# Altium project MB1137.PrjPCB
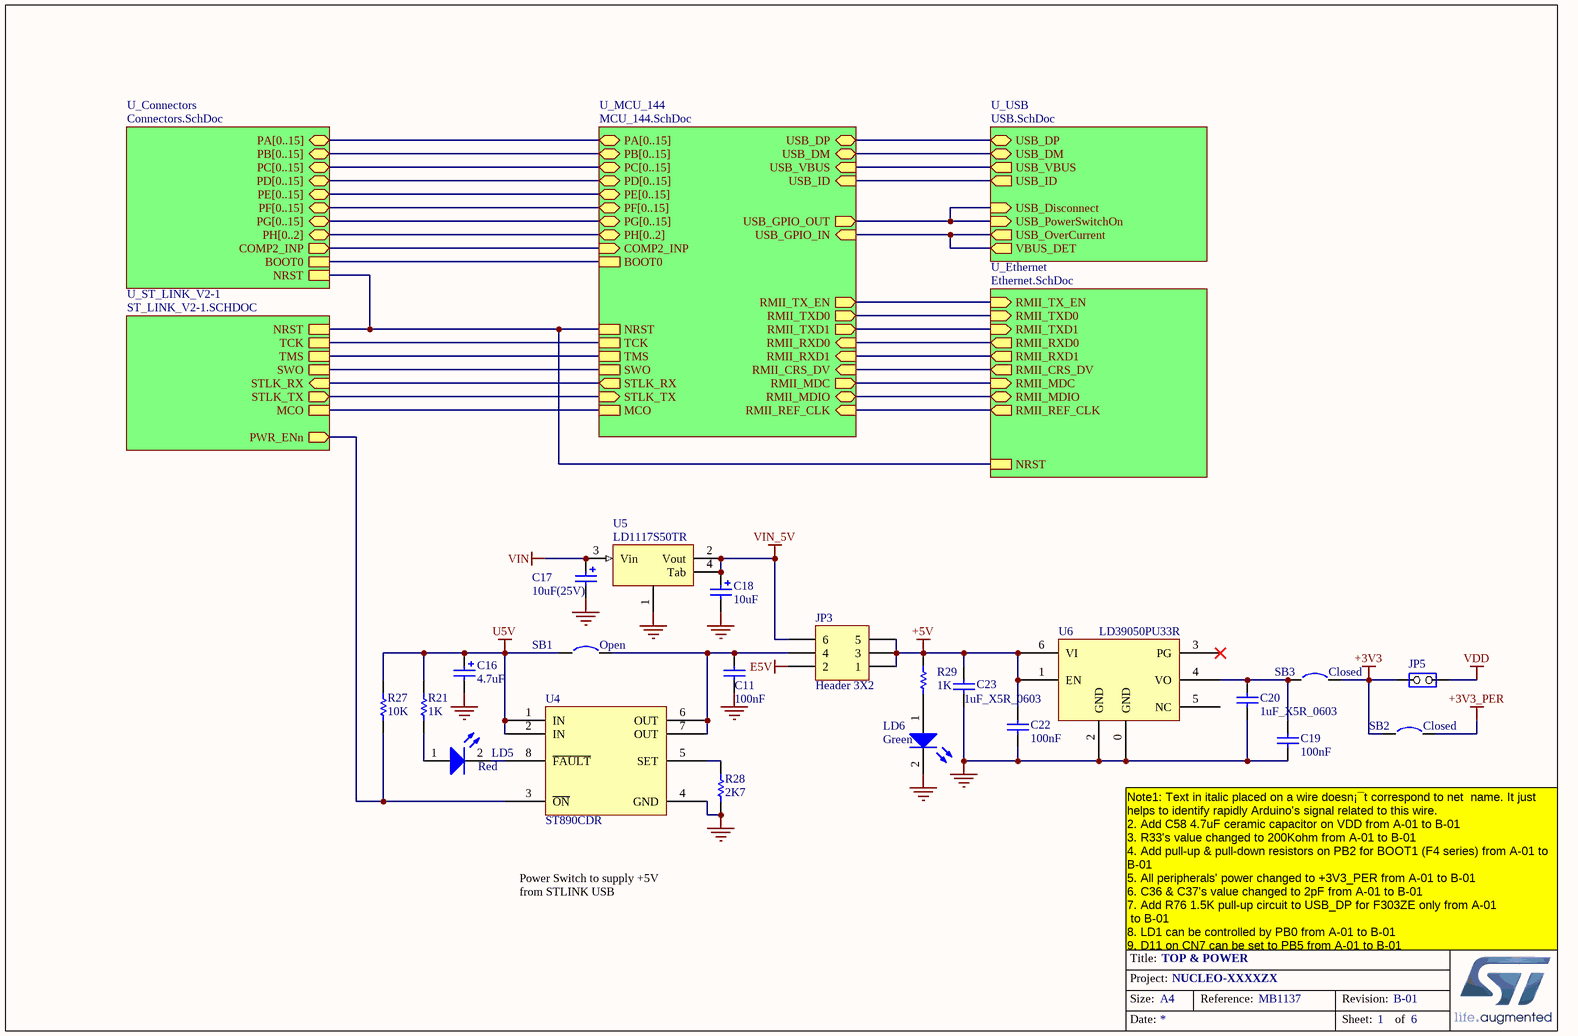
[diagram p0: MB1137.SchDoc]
6 sheets, 293 parts. Net scope: hierarchical (ports join the sheet entries above them; power ports are global).
Sheets:
  MB1137.SchDoc
    U_Connectors = Connectors.SchDoc
    U_ST_LINK_V2-1 = ST_LINK_V2-1.SCHDOC
    U_Ethernet = Ethernet.SchDoc
    U_MCU_144 = MCU_144.SchDoc
    U_USB = USB.SchDoc

## Sheet MB1137.SchDoc: TOP & POWER
size A4; DocumentNumber: MB1137; Revision: B-01; SheetNumber: 1; SheetTotal: 6; Project: NUCLEO-XXXXZX

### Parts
C11  100nF  [0603C]
C16  4.7uF  [TAN-A]
C17  10uF(25V)  [TAN-B]
C18  10uF  [TAN-A]
C19  100nF  [0603C]
C20  1uF_X5R_0603  [0603C]
C22  100nF  [0603C]
C23  1uF_X5R_0603  [0603C]
JP3  Header 3X2  [HDR_3x2_2R54_V_M]
JP5  (no value)  [HDR_1x2_2R54_V_M_S]
LD5  Red  [0603D-R]
LD6  Green  [0603D-G]
R21  1K  [0603R]
R27  10K  [0603R]
R28  2K7  [0603R]
R29  1K  [0603R]
SB1  Open  [SB_0603]
SB2  Closed  [SB_0603]
SB3  Closed  [SB_0603]
U4  ST890CDR  [SOIC8_1R27_4R9X6]
U5  LD1117S50TR  [SOT-223]
U6  LD39050PU33R  [DFN6_0R95_3x3_TP]

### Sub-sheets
U_Connectors = Connectors.SchDoc: PA[0..15] (bidir), PB[0..15] (bidir), PC[0..15] (bidir), NRST, BOOT0, PD[0..15] (bidir), PE[0..15] (bidir), PF[0..15] (bidir), PG[0..15] (bidir), PH[0..2] (bidir), COMP2_INP (out)
U_Ethernet = Ethernet.SchDoc: RMII_TXD0 (in), RMII_TX_EN (in), RMII_RXD0 (out), RMII_REF_CLK (out), RMII_CRS_DV (out), RMII_MDC (in), RMII_MDIO (bidir), NRST, RMII_TXD1 (in), RMII_RXD1 (out)
U_MCU_144 = MCU_144.SchDoc: NRST, MCO, STLK_TX (in), STLK_RX (out), PA[0..15] (bidir), PB[0..15] (bidir), PC[0..15] (bidir), TCK, TMS, SWO, BOOT0, PD[0..15] (bidir), PE[0..15] (bidir), PF[0..15] (bidir), PG[0..15] (bidir), PH[0..2] (bidir), USB_DM (bidir), USB_DP (bidir), USB_GPIO_OUT (out), USB_GPIO_IN (in), USB_ID (in), USB_VBUS (in), RMII_TXD0 (out), RMII_TX_EN (out), RMII_RXD0 (in), RMII_REF_CLK (in), RMII_CRS_DV (in), RMII_MDC (out), RMII_MDIO (bidir), RMII_TXD1 (out), RMII_RXD1 (in), COMP2_INP (in)
U_ST_LINK_V2-1 = ST_LINK_V2-1.SCHDOC: TMS, TCK, MCO, NRST, STLK_RX (in), STLK_TX (out), SWO, PWR_ENn (out)
U_USB = USB.SchDoc: USB_PowerSwitchOn (in), USB_OverCurrent (out), USB_DM (bidir), USB_DP (bidir), USB_ID (out), USB_VBUS (out), USB_Disconnect (in), VBUS_DET (out)

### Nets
+3V3: JP5.1(COMMON) SB2.1 SB3.2
+3V3_PER: SB2.2
+5V: C22.2 C23.1 JP3.1 JP3.3 JP3.5 R29.2 U6.1(EN) U6.6(VI)
E5V: JP3.2
GND: C11.1 C16.2 C17.2 C18.2 C19.1 C20.2 C22.1 C23.2 LD6.2(K) R28.1 U4.4(GND) U5.1 U6.0(GND) U6.2(GND)
U5V: C16.1 R21.1 R27.1 SB1.1 U4.1(IN) U4.2(IN)
VDD: JP5.2(NO)
VIN: C17.1 U5.3(Vin)
VIN_5V: C18.1 JP3.6 U5.2(Vout) U5.4(Tab)
BOOT0: sheet U_Connectors/BOOT0, sheet U_MCU_144/BOOT0
MCO: sheet U_ST_LINK_V2-1/MCO, sheet U_MCU_144/MCO
NRST: sheet U_Connectors/NRST, sheet U_ST_LINK_V2-1/NRST, sheet U_Ethernet/NRST, sheet U_MCU_144/NRST
PA13: sheet U_ST_LINK_V2-1/TMS, sheet U_MCU_144/TMS
PA14: sheet U_ST_LINK_V2-1/TCK, sheet U_MCU_144/TCK
PB3: sheet U_ST_LINK_V2-1/SWO, sheet U_MCU_144/SWO
PG6: sheet U_MCU_144/USB_GPIO_OUT, sheet U_USB/USB_PowerSwitchOn, sheet U_USB/USB_Disconnect
NetC11_2: C11.2 JP3.4 SB1.2 U4.6(OUT) U4.7(OUT)
NetC19_2: C19.2 C20.1 SB3.1 U6.4(VO)
NetC54_1: sheet U_MCU_144/USB_VBUS, sheet U_USB/USB_VBUS
NetCN5_1: sheet U_ST_LINK_V2-1/STLK_RX, sheet U_MCU_144/STLK_RX
NetCN5_2: sheet U_ST_LINK_V2-1/STLK_TX, sheet U_MCU_144/STLK_TX
NetCN9_15: sheet U_Connectors/COMP2_INP, sheet U_Ethernet/RMII_CRS_DV, sheet U_MCU_144/RMII_CRS_DV, sheet U_MCU_144/COMP2_INP
NetCN13_2: sheet U_MCU_144/USB_DM, sheet U_USB/USB_DM
NetCN13_3: sheet U_MCU_144/USB_DP, sheet U_USB/USB_DP
NetCN13_4: sheet U_MCU_144/USB_ID, sheet U_USB/USB_ID
NetJP4_1: sheet U_MCU_144/USB_GPIO_IN, sheet U_USB/USB_OverCurrent, sheet U_USB/VBUS_DET
NetJP7_1: sheet U_Ethernet/RMII_TXD1, sheet U_MCU_144/RMII_TXD1
NetLD5_1: LD5.1(A) R21.2
NetLD5_2: LD5.2(K) U4.8(~{FAULT})
NetLD6_1: LD6.1(A) R29.1
NetR27_2: R27.2 U4.3(~{ON}) ; sheet U_ST_LINK_V2-1/PWR_ENn
NetR28_2: R28.2 U4.5(SET)
NetR42_2: sheet U_Ethernet/RMII_RXD0, sheet U_MCU_144/RMII_RXD0
NetR45_2: sheet U_Ethernet/RMII_RXD1, sheet U_MCU_144/RMII_RXD1
NetR46_1: sheet U_Ethernet/RMII_MDIO, sheet U_MCU_144/RMII_MDIO
NetR48_2: sheet U_Ethernet/RMII_REF_CLK, sheet U_MCU_144/RMII_REF_CLK
NetSB164_1: sheet U_Ethernet/RMII_MDC, sheet U_MCU_144/RMII_MDC
NetSB182_2: sheet U_Ethernet/RMII_TXD0, sheet U_MCU_144/RMII_TXD0
NetSB183_2: sheet U_Ethernet/RMII_TX_EN, sheet U_MCU_144/RMII_TX_EN

Not connected (* = marked no-connect by the designer): U6 3(PG)* 5(NC)

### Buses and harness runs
bus sheet U_Connectors/PA[0..15] = sheet U_MCU_144/PA[0..15]
bus sheet U_Connectors/PB[0..15] = sheet U_MCU_144/PB[0..15]
bus sheet U_Connectors/PC[0..15] = sheet U_MCU_144/PC[0..15]
bus sheet U_Connectors/PD[0..15] = sheet U_MCU_144/PD[0..15]
bus sheet U_Connectors/PE[0..15] = sheet U_MCU_144/PE[0..15]
bus sheet U_Connectors/PF[0..15] = sheet U_MCU_144/PF[0..15]
bus sheet U_Connectors/PG[0..15] = sheet U_MCU_144/PG[0..15]
bus sheet U_Connectors/PH[0..2] = sheet U_MCU_144/PH[0..2]

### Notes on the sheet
- Power Switch to supply +5V from STLINK USB
- Note1: Text in italic placed on a wire doesn¡¯t correspond to net  name. It just helps to identify rapidly Arduino's signal related to this wire.
  2. Add C58 4.7uF ceramic capacitor on VDD from A-01 to B-01
  3. R33's value changed to 200Kohm from A-01 to B-01
  4. Add pull-up & pull-down resistors on PB2 for BOOT1 (F4 series) from A-01 to B-01
  5. All peripherals' power changed to +3V3_PER from A-01 to B-01
  6. C36 & C37's value changed to 2pF from A-01 to B-01
  7. Add R76 1.5K pull-up circuit to USB_DP for F303ZE only from A-01
  to B-01
  8. LD1 can be controlled by PB0 from A-01 to B-01
  9. D11 on CN7 can be set to PB5 from A-01 to B-01

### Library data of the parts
C11 C19 C22 = Capacitor_ST: Capacitor 0402 / 0603 / 0805
C16 = Cap Pol1: Polarized Capacitor (Radial); Value: 100pF; Ordered by: Subcon
C17 C18 = Cap Pol1: Polarized Capacitor (Radial)
C20 C23 = CAP SMD 0603  X5R 1µF 25V 10%: 0603  X5R 1µF; Rated voltage: 25V; Tolerance: 10%
JP3 = Header 3X2: Header, 3-Pin, Dual row
JP5 = JP2
LD5 LD6 = LED2: Typical RED, GREEN, YELLOW, AMBER GaAs LED
R21 = Res1: Resistor; Ordered by: Subcon
R27 = Resistor_ST: Resistor 0402 / 0603 / 0805; Description: Resistor 0402 or 0603 or 0805
R28 R29 = Resistor_ST: Resistor 0402 / 0603 / 0805; Description: Resistor 0402 or 0603 or 0805; Value: 10K
SB1 = Circuit Breaker
SB2 SB3 = Circuit Breaker_close: Circuit Breaker
U5 = LD1117
U6 = LD39050P

## Sheet Connectors.SchDoc: Extension connectors
size A3; DocumentNumber: MB1137; Revision: B-01; SheetNumber: 6; SheetTotal: 6; Project: NUCLEO-XXXXZX
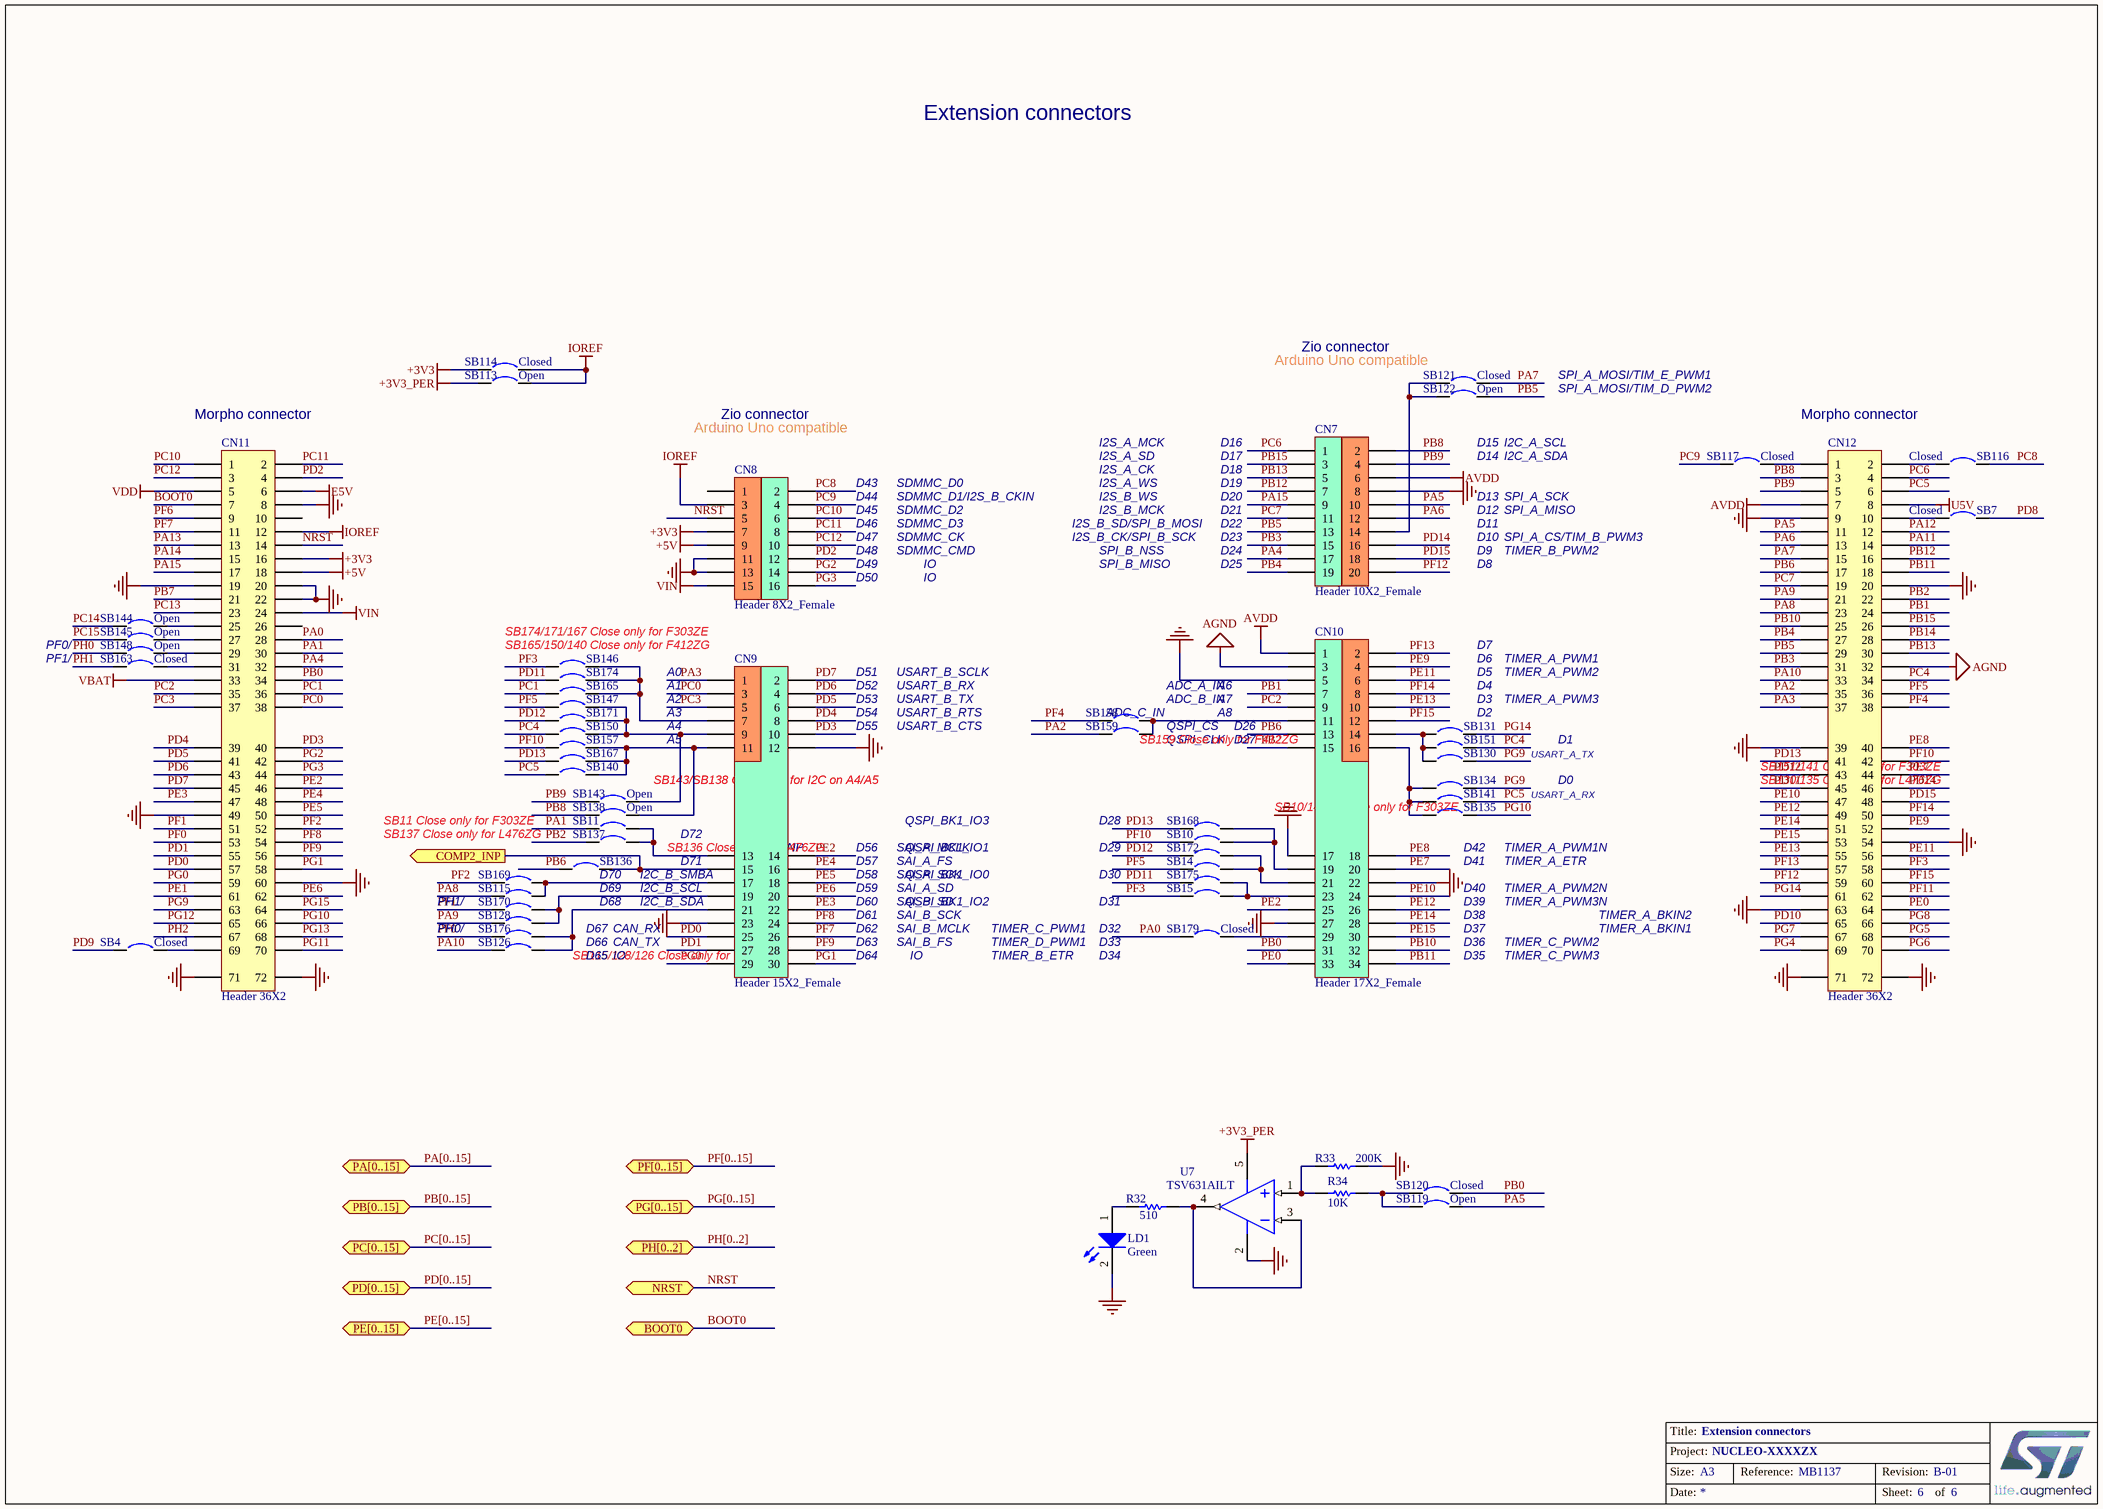
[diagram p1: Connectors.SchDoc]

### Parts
CN7  Header 10X2_Female  [HDR_10x2_2R54_V_F]
CN8  Header 8X2_Female  [HDR_8x2_2R54_V_F]
CN9  Header 15X2_Female  [HDR_15x2_2R54_V_F]
CN10  Header 17X2_Female  [HDR_17x2_2R54_V_F]
CN11  Header 36X2  [HDR_2x36_2R54_V_M]
CN12  Header 36X2  [HDR_2x36_2R54_V_M]
LD1  Green  [0603D-G]
R32  510  [0603R]
R33  200K  [0603R]
R34  10K  [0603R]
SB4  Closed  [SB_0603]
SB7  Closed  [SB_0603]
SB10  Circuit Breaker  [SB_0603]  (value not drawn)
SB11  Circuit Breaker  [SB_0603]  (value not drawn)
SB14  Circuit Breaker  [SB_0603]  (value not drawn)
SB15  Circuit Breaker  [SB_0603]  (value not drawn)
SB113  Open  [SB_0603]
SB114  Closed  [SB_0603]
SB115  Circuit Breaker  [SB_0603]  (value not drawn)
SB116  Closed  [SB_0603]
SB117  Closed  [SB_0603]
SB119  Open  [SB_0603]
SB120  Closed  [SB_0603]
SB121  Closed  [SB_0603]
SB122  Open  [SB_0603]
SB126  Circuit Breaker  [SB_0603]  (value not drawn)
SB128  Circuit Breaker  [SB_0603]  (value not drawn)
SB130  Circuit Breaker  [SB_0603]  (value not drawn)
SB131  Circuit Breaker  [SB_0603]  (value not drawn)
SB134  Circuit Breaker  [SB_0603]  (value not drawn)
SB135  Circuit Breaker  [SB_0603]  (value not drawn)
SB136  Circuit Breaker  [SB_0603]  (value not drawn)
SB137  Circuit Breaker  [SB_0603]  (value not drawn)
SB138  Open  [SB_0603]
SB140  Circuit Breaker  [SB_0603]  (value not drawn)
SB141  Circuit Breaker  [SB_0603]  (value not drawn)
SB143  Open  [SB_0603]
SB144  Open  [SB_0603]
SB145  Open  [SB_0603]
SB146  Circuit Breaker  [SB_0603]  (value not drawn)
SB147  Circuit Breaker  [SB_0603]  (value not drawn)
SB148  Open  [SB_0603]
SB150  Circuit Breaker  [SB_0603]  (value not drawn)
SB151  Circuit Breaker  [SB_0603]  (value not drawn)
SB157  Circuit Breaker  [SB_0603]  (value not drawn)
SB158  Circuit Breaker  [SB_0603]  (value not drawn)
SB159  Circuit Breaker  [SB_0603]  (value not drawn)
SB163  Closed  [SB_0603]
SB165  Circuit Breaker  [SB_0603]  (value not drawn)
SB167  Circuit Breaker  [SB_0603]  (value not drawn)
SB168  Circuit Breaker  [SB_0603]  (value not drawn)
SB169  Circuit Breaker  [SB_0603]  (value not drawn)
SB170  Circuit Breaker  [SB_0603]  (value not drawn)
SB171  Circuit Breaker  [SB_0603]  (value not drawn)
SB172  Circuit Breaker  [SB_0603]  (value not drawn)
SB174  Circuit Breaker  [SB_0603]  (value not drawn)
SB175  Circuit Breaker  [SB_0603]  (value not drawn)
SB176  Circuit Breaker  [SB_0603]  (value not drawn)
SB179  Closed  [SB_0603]
U7  TSV631AILT  [SOT-23-5L]

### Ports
BOOT0, COMP2_INP (out), NRST, PA[0..15] (bidir), PB[0..15] (bidir), PC[0..15] (bidir), PD[0..15] (bidir), PE[0..15] (bidir), PF[0..15] (bidir), PG[0..15] (bidir), PH[0..2] (bidir)

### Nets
+3V3: CN8.7 CN11.16 SB114.1
+3V3_PER: SB113.1 U7.5(VCC)
+5V: CN8.9 CN11.18
AGND: CN10.3 CN12.32
AVDD: CN7.6 CN10.1 CN12.7
E5V: CN11.6
GND: CN7.8 CN8.11 CN8.13 CN9.12 CN9.23 CN10.5 CN10.17 CN10.22 CN10.27 CN11.8 CN11.19 CN11.20 CN11.22 CN11.49 CN11.60 CN11.71 CN11.72 CN12.9 CN12.20 CN12.39 CN12.54 CN12.63 CN12.71 CN12.72 LD1.2(K) R33.2 U7.2(VDD)
IOREF: CN8.3 CN11.12 SB113.2 SB114.2
U5V: CN12.8
VBAT: CN11.33
VDD: CN11.5
VIN: CN8.15 CN11.24
BOOT0: CN11.7 ; port BOOT0
NRST: CN8.5 CN11.14 ; port NRST
PA0: CN11.28 SB179.1
PA1: CN11.30 SB11.2
PA2: CN12.35 SB159.1
PA3: CN9.1 CN12.37
PA4: CN7.17 CN11.32
PA5: CN7.10 CN12.11 SB119.2
PA6: CN7.12 CN12.13
PA7: CN12.15 SB121.2
PA8: CN12.23 SB115.2
PA9: CN12.21 SB128.2
PA10: CN12.33 SB126.2
PA11: CN12.14
PA12: CN12.12
PA13: CN11.13
PA14: CN11.15
PA15: CN7.9 CN11.17
PB0: CN10.31 CN11.34 SB120.1
PB1: CN10.7 CN12.24
PB2: CN10.15 CN12.22 SB137.2
PB3: CN7.15 CN12.31
PB4: CN7.19 CN12.27
PB5: CN7.13 CN12.29 SB122.2
PB6: CN10.13 CN12.17 SB136.2
PB7: CN11.21
PB8: CN7.2 CN12.3 SB138.2
PB9: CN7.4 CN12.5 SB143.2
PB10: CN10.32 CN12.25
PB11: CN10.34 CN12.18
PB12: CN7.7 CN12.16
PB13: CN7.5 CN12.30
PB14: CN12.28
PB15: CN7.3 CN12.26
PC0: CN9.3 CN11.38
PC1: CN11.36 SB165.2
PC2: CN10.9 CN11.35
PC3: CN9.5 CN11.37
PC4: CN12.34 SB150.2 SB151.1
PC5: CN12.6 SB140.2 SB141.1
PC6: CN7.1 CN12.4
PC7: CN7.11 CN12.19
PC8: CN8.2 SB116.1
PC9: CN8.4 SB117.1
PC10: CN8.6 CN11.1
PC11: CN8.8 CN11.2
PC12: CN8.10 CN11.3
PC13: CN11.23
PC14: SB144.1
PC15: SB145.1
PD0: CN9.25 CN11.57
PD1: CN9.27 CN11.55
PD2: CN8.12 CN11.4
PD3: CN9.10 CN11.40
PD4: CN9.8 CN11.39
PD5: CN9.6 CN11.41
PD6: CN9.4 CN11.43
PD7: CN9.2 CN11.45
PD8: SB7.2
PD9: SB4.1
PD10: CN12.65
PD11: CN12.45 SB174.2 SB175.1
PD12: CN12.43 SB171.2 SB172.1
PD13: CN12.41 SB167.2 SB168.1
PD14: CN7.16 CN12.46
PD15: CN7.18 CN12.48
PE0: CN10.33 CN12.64
PE1: CN11.61
PE2: CN9.14 CN10.25 CN11.46
PE3: CN9.22 CN11.47
PE4: CN9.16 CN11.48
PE5: CN9.18 CN11.50
PE6: CN9.20 CN11.62
PE7: CN10.20 CN12.44
PE8: CN10.18 CN12.40
PE9: CN10.4 CN12.52
PE10: CN10.24 CN12.47
PE11: CN10.6 CN12.56
PE12: CN10.26 CN12.49
PE13: CN10.10 CN12.55
PE14: CN10.28 CN12.51
PE15: CN10.30 CN12.53
PF0: CN11.53 SB176.2
PF1: CN11.51 SB170.2
PF2: CN11.52 SB169.2
PF3: CN12.58 SB15.1 SB146.2
PF4: CN12.38 SB158.1
PF5: CN12.36 SB14.1 SB147.2
PF6: CN11.9
PF7: CN9.26 CN11.11
PF8: CN9.24 CN11.54
PF9: CN9.28 CN11.56
PF10: CN12.42 SB10.1 SB157.2
PF11: CN12.62
PF12: CN7.20 CN12.59
PF13: CN10.2 CN12.57
PF14: CN10.8 CN12.50
PF15: CN10.12 CN12.60
PG0: CN9.29 CN11.59
PG1: CN9.30 CN11.58
PG2: CN8.14 CN11.42
PG3: CN8.16 CN11.44
PG4: CN12.69
PG5: CN12.68
PG6: CN12.70
PG7: CN12.67
PG8: CN12.66
PG9: CN11.63 SB130.1 SB134.1
PG10: CN11.66 SB135.1
PG11: CN11.70
PG12: CN11.65
PG13: CN11.68
PG14: CN12.61 SB131.1
PG15: CN11.64
PH0: SB148.1
PH1: SB163.1
PH2: CN11.67
NetCN7_14: CN7.14 SB121.1 SB122.1
NetCN9_7: CN9.7 SB146.1 SB165.1 SB174.1
NetCN9_9: CN9.9 SB143.1 SB147.1 SB150.1 SB171.1
NetCN9_11: CN9.11 SB138.1 SB140.1 SB157.1 SB167.1
NetCN9_13: CN9.13 SB11.1 SB137.1
NetCN9_15: CN9.15 SB136.1 ; port COMP2_INP
NetCN9_17: CN9.17 SB115.1 SB169.1
NetCN9_19: CN9.19 SB128.1 SB170.1
NetCN9_21: CN9.21 SB126.1 SB176.1
NetCN10_11: CN10.11 SB158.2 SB159.2
NetCN10_14: CN10.14 SB130.2 SB131.2 SB151.2
NetCN10_16: CN10.16 SB134.2 SB135.2 SB141.2
NetCN10_19: CN10.19 SB10.2 SB168.2
NetCN10_21: CN10.21 SB14.2 SB172.2
NetCN10_23: CN10.23 SB15.2 SB175.2
NetCN10_29: CN10.29 SB179.2
NetCN11_25: CN11.25 SB144.2
NetCN11_27: CN11.27 SB145.2
NetCN11_29: CN11.29 SB148.2
NetCN11_31: CN11.31 SB163.2
NetCN11_69: CN11.69 SB4.2
NetCN12_1: CN12.1 SB117.2
NetCN12_2: CN12.2 SB116.2
NetCN12_10: CN12.10 SB7.1
NetLD1_1: LD1.1(A) R32.2
NetR32_1: R32.1 U7.3(IN-) U7.4(OUT)
NetR33_1: R33.1 R34.1 U7.1(IN+)
NetR34_2: R34.2 SB119.1 SB120.2

Not connected (* = marked no-connect by the designer): CN8 1; CN11 10 26

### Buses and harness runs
bus PA[0..15] = port PA[0..15]
bus PB[0..15] = port PB[0..15]
bus PC[0..15] = port PC[0..15]
bus PD[0..15] = port PD[0..15]
bus PE[0..15] = port PE[0..15]
bus PF[0..15] = port PF[0..15]
bus PG[0..15] = port PG[0..15]
bus PH[0..2] = port PH[0..2]

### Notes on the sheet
- Extension connectors
- Arduino Uno compatible
- Zio connector
- SPI_A_MOSI/TIM_E_PWM1
- (near CN11) Morpho connector
- I2S_A_MCK
- D16
- D15
- I2C_A_SCL
- SPI_A_MOSI/TIM_D_PWM2
- Morpho connector
- D43
- D44
- D45
- SDMMC_D0
- SDMMC_D1/I2S_B_CKIN
- SDMMC_D2
- I2S_A_SD
- I2S_A_CK
- I2S_A_WS
- I2S_B_WS
- I2S_B_MCK
- D17
- D18
- D19
- D20
- D21
- D14
- D13
- D12
- SPI_A_SCK
- SPI_A_MISO
- I2C_A_SDA
- D46
- D47
- D48
- D49
- D50
- SDMMC_CK
- SDMMC_CMD
- SDMMC_D3
- IO
- I2S_B_SD/SPI_B_MOSI
- I2S_B_CK/SPI_B_SCK
- SPI_B_MISO
- SPI_B_NSS
- D22
- D23
- D24
- D25
- D8
- D9
- D10
- D11
- TIMER_B_PWM2
- SPI_A_CS/TIM_B_PWM3
- PF0/
- SB174/171/167 Close only for F303ZE
- (near SB146) SB165/150/140 Close only for F412ZG
- D7
- PF1/
- A0
- A1
- A2
- A3
- D51
- D52
- D53
- D54
- USART_B_TX
- USART_B_RX
- USART_B_SCLK
- USART_B_RTS
- ADC_A_IN
- ADC_B_IN
- ADC_C_IN
- A6
- A7
- A8
- (near SB131) D2
- D4
- D3
- D5
- D6
- TIMER_A_PWM1
- TIMER_A_PWM2
- TIMER_A_PWM3
- (near SB140) SB143/SB138 Close only for I2C on A4/A5
- A4
- A5
- D55
- USART_B_CTS
- (near SB159) SB159 Close only for F412ZG
- QSPI_CLK
- QSPI_CS
- D26
- D27
- USART_A_TX
- D0
- D1
- SB151/141 Close only for F303ZE
- SB130/135 Close only for L476ZG
- (near CN11) /PH1
- (near CN11) /PH0
- SB11 Close only for F303ZE
- SB137 Close only for L476ZG
- (near SB137) SB136 Close only for L476ZG
- D72
- (near CN9) COMP1_INP
- D56
- SAI_A_MCLK
- QSPI_BK1_IO1
- QSPI_BK1_IO3
- D28
- D29
- (near SB168) SB10/14/15 Close only for F303ZE
- D42
- TIMER_A_PWM1N
- USART_A_RX
- PH1/
- (near SB136) D70
- (near SB136) D69
- (near SB136) D68
- I2C_B_SCL
- I2C_B_SDA
- I2C_B_SMBA
- D71
- D57
- D58
- D59
- D60
- D61
- SAI_A_SD
- SAI_A_SCK
- SAI_A_FS
- SAI_B_SD
- SAI_B_SCK
- QSPI_BK1_IO0
- QSPI_BK1_IO2
- D30
- D31
- D38
- D39
- D40
- D41
- TIMER_A_PWM2N
- TIMER_A_PWM3N
- TIMER_A_ETR
- TIMER_A_BKIN2
- PH0/
- (near SB126) SB115/128/126 Close only for F303ZE
- D67
- D66
- D65
- CAN_TX
- CAN_RX
- D62
- D63
- D64
- SAI_B_FS
- SAI_B_MCLK
- TIMER_D_PWM1
- TIMER_B_ETR
- TIMER_C_PWM1
- D32
- D33
- D34
- D35
- D36
- D37
- TIMER_C_PWM2
- TIMER_C_PWM3
- TIMER_A_BKIN1

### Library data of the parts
CN7 = Header 10X2_Female: Header, 10-Pin, Dual row,female
CN8 = Header 8X2_Female: Header, 8-Pin, Dual row,female
CN9 = Header 15X2_Female: Header, 15-Pin, Dual row,female
CN10 = Header 17X2_Female: Header, 17-Pin, Dual row,female
CN11 CN12 = Header 36X2: Header, 36-Pin, Dual row
LD1 = LED2: as LD5 on sheet MB1137
R32 = Res1: Resistor; Value: 1K
R33 R34 = res1: Resistor; Value: 1K
SB4 SB7 SB114 SB116 SB117 SB120 SB121 SB163 SB179 = Circuit Breaker_close: Circuit Breaker
SB10 SB11 SB14 SB15 SB115 SB126 SB128 SB130 SB131 SB134-SB137 SB140 SB141 SB146 SB147 SB150 SB151 SB157-SB159 SB165 SB167-SB172 SB174-SB176 = Circuit Breaker: Solder: NO
SB113 SB119 SB122 SB138 SB143-SB145 SB148 = Circuit Breaker

## Sheet ST_LINK_V2-1.SCHDOC: STLINK/V2-1
size A4; DocumentNumber: MB1137; Revision: B-01; SheetNumber: 3; SheetTotal: 6; Project: NUCLEO-XXXXZX
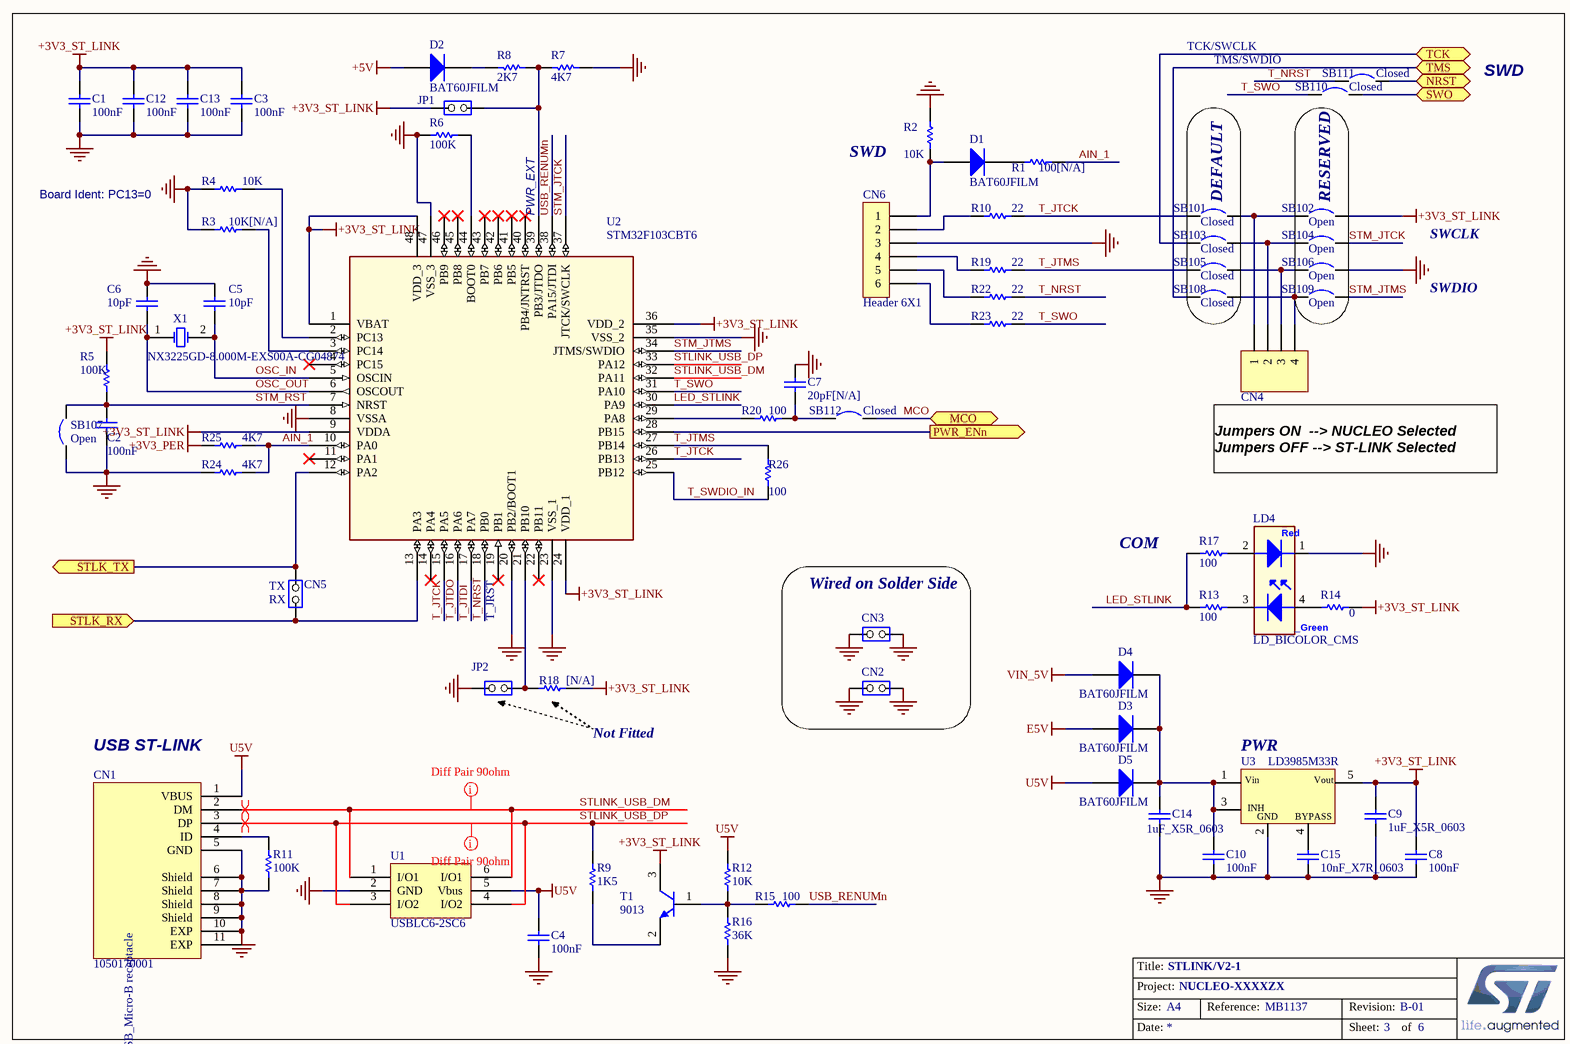
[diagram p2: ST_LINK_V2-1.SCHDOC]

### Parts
C1  100nF  [0603C]
C2  100nF  [0603C]
C3  100nF  [0603C]
C4  100nF  [0603C]
C5  10pF  [0603C]
C6  10pF  [0603C]
C7  20pF[N/A]  [0603C]
C8  100nF  [0603C]
C9  1uF_X5R_0603  [0603C]
C10  100nF  [0603C]
C12  100nF  [0603C]
C13  100nF  [0603C]
C14  1uF_X5R_0603  [0603C]
C15  10nF_X7R_0603  [0603C]
CN1  1050170001  [Molex_1050170001]
CN2  (no value)  [HDR_1x2_2R54_V_M]
CN3  (no value)  [HDR_1x2_2R54_V_M]
CN4  Header 4  [HDR_1x4_2R54_V_M]  (value not drawn)
CN5  (no value)  [HDR_1x2_2R54_V_M_S]
CN6  Header 6X1  [HDR_1x6_2R54_V_M]
D1  BAT60JFILM  [SOD-323]
D2  BAT60JFILM  [SOD-323]
D3  BAT60JFILM  [SOD-323]
D4  BAT60JFILM  [SOD-323]
D5  BAT60JFILM  [SOD-323]
JP1  (no value)  [HDR_1x2_2R54_V_M_S]
JP2  (no value)  [HDR_1x2_2R54_V_M_S]
LD4  LD_BICOLOR_CMS  [HSMF-A201]
R1  100[N/A]  [0603R]
R2  10K  [0603R]
R3  10K[N/A]  [0603R]
R4  10K  [0603R]
R5  100K  [0603R]
R6  100K  [0603R]
R7  4K7  [0603R]
R8  2K7  [0603R]
R9  1K5  [0603R]
R10  22  [0603R]
R11  100K  [0603R]
R12  10K  [0603R]
R13  100  [0603R]
R14  0  [0603R]
R15  100  [0603R]
R16  36K  [0603R]
R17  100  [0603R]
R18  [N/A]  [0603R]
R19  22  [0603R]
R20  100  [0603R]
R22  22  [0603R]
R23  22  [0603R]
R24  4K7  [0603R]
R25  4K7  [0603R]
R26  100  [0603R]
SB101  Closed  [SB_0603]
SB102  Open  [SB_0603]
SB103  Closed  [SB_0603]
SB104  Open  [SB_0603]
SB105  Closed  [SB_0603]
SB106  Open  [SB_0603]
SB107  Open  [SB_0603]
SB108  Closed  [SB_0603]
SB109  Open  [SB_0603]
SB110  Closed  [SB_0603]
SB111  Closed  [SB_0603]
SB112  Closed  [SB_0603]
T1  9013  [SOT-23]
U1  USBLC6-2SC6  [SOT23-6L]
U2  STM32F103CBT6  [LQFP48_0R5_7x7]
U3  LD3985M33R  [SOT-23-5L]
X1  NX3225GD-8.000M-EXS00A-CG04874  [OSC_2SM_3R2x2R5]

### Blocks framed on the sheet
DEFAULT: SB101 SB103 SB105 SB108
RESERVED: SB102 SB104 SB106 SB109
Wired on Solder Side: CN2 CN3

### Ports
MCO, NRST, PWR_ENn (out), STLK_RX (in), STLK_TX (out), SWO, TCK, TMS

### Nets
+3V3_PER: R25.1
+3V3_ST_LINK: C1.2 C3.2 C8.2 C9.1 C12.2 C13.2 JP1.1(COMMON) R5.2 R14.2 R18.1 SB102.2 T1.3(C) U2.1(VBAT) U2.9(VDDA) U2.24(VDD_1) U2.36(VDD_2) U2.48(VDD_3) U3.5(Vout)
+5V: D2.1(A)
E5V: D3.1(A)
GND: C1.1 C2.1 C3.1 C4.1 C5.2 C6.2 C7.2 C8.1 C9.2 C10.1 C12.1 C13.1 C14.1 C15.1 CN1.5(GND) CN1.6(Shield) CN1.7(Shield) CN1.8(Shield) CN1.9(Shield) CN1.10(EXP) CN2.1(COMMON) CN2.2(NO) CN3.1(COMMON) CN3.2(NO) CN6.3 JP2.1(COMMON) LD4.1 R2.2 R3.1 R4.1 R6.1 R7.2 R11.2 R16.1 R24.1 SB106.2 SB107.1 U1.2(GND) U2.8(VSSA) U2.20(PB2/BOOT1) U2.23(VSS_1) U2.35(VSS_2) U2.47(VSS_3) U3.2(GND)
U5V: C4.2 CN1.1(VBUS) D5.1(A) R12.2 U1.5(Vbus)
VIN_5V: D4.1(A)
AIN_1: R1.2 R24.2 R25.2 U2.10(PA0)
LED_STLINK: R13.1 R17.1 U2.30(PA9)
MCO: SB112.2 ; port MCO
NRST: SB111.2 ; port NRST
OSC_IN: C5.1 U2.5(OSCIN) X1.2(OSC2)
OSC_OUT: C6.1 U2.6(OSCOUT) X1.1(OSC1)
PA13: SB108.1 ; port TMS
PA14: SB103.1 ; port TCK
PB3: SB110.2 ; port SWO
STLINK_USB_DM: CN1.2(DM) U1.1(I/O1) U1.6(I/O1) U2.32(PA11)
STLINK_USB_DP: CN1.3(DP) R9.1 U1.3(I/O2) U1.4(I/O2) U2.33(PA12)
STM_JTCK: SB104.2 U2.37(JTCK/SWCLK)
STM_JTMS: SB109.2 U2.34(JTMS/SWDIO)
STM_RST: C2.2 R5.1 SB107.2 U2.7(NRST)
T_JTCK: R10.2 SB101.1 U2.15(PA5) U2.26(PB13)
T_JTDI: U2.17(PA7)
T_JTDO: U2.16(PA6)
T_JTMS: R19.2 R26.2 SB105.1 U2.27(PB14)
T_NRST: R22.2 SB111.1 U2.18(PB0)
T_SWDIO_IN: R26.1 U2.25(PB12)
T_SWO: R23.2 SB110.1 U2.31(PA10)
USB_RENUMn: R15.2 U2.38(PA15/JTDI)
NetC7_1: C7.1 R20.2 SB112.1
NetC10_2: C10.2 C14.2 D3.2(K) D4.2(K) D5.2(K) U3.1(Vin) U3.3(CE)
NetC15_2: C15.2 U3.4(BYPASS)
NetCN1_4: CN1.4(ID) R11.1
NetCN4_1: CN4.1 SB101.2 SB102.1
NetCN4_2: CN4.2 SB103.2 SB104.1
NetCN4_3: CN4.3 SB105.2 SB106.1
NetCN4_4: CN4.4 SB108.2 SB109.1
NetCN5_1: CN5.1(COMMON) U2.13(PA3) ; port STLK_RX
NetCN5_2: CN5.2(NO) U2.12(PA2) ; port STLK_TX
NetCN6_1: CN6.1 D1.1(A) R2.1
NetCN6_2: CN6.2 R10.1
NetCN6_4: CN6.4 R19.1
NetCN6_5: CN6.5 R22.1
NetCN6_6: CN6.6 R23.1
NetD1_2: D1.2(K) R1.1
NetD2_2: D2.2(K) R8.1
NetJP1_2: JP1.2(NO) R7.1 R8.2 U2.39(PB3/JTDO)
NetJP2_2: JP2.2(NO) R18.2 U2.21(PB10)
NetLD4_2: LD4.2 R17.2
NetLD4_3: LD4.3 R13.2
NetLD4_4: LD4.4 R14.1
NetR3_2: R3.2 U2.3(PC14)
NetR4_2: R4.2 U2.2(PC13)
NetR6_2: R6.2 U2.44(BOOT0)
NetR9_2: R9.2 T1.2(E)
NetR12_1: R12.1 R15.1 R16.2 T1.1(B)
NetR20_1: R20.1 U2.29(PA8)
NetR27_2: U2.28(PB15) ; port PWR_ENn

Not connected (* = marked no-connect by the designer): CN1 11(EXP); U2 4(PC15)* 11(PA1)* 14(PA4)* 19(PB1)* 22(PB11)* 40(PB4/JNTRST)* 41(PB5)* 42(PB6)* 43(PB7)* 45(PB8)* 46(PB9)*

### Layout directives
differential pair: (no net found under the mark)
mark named Diff Pair 90ohm: STLINK_USB_DM, STLINK_USB_DP

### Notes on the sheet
- TCK/SWCLK
- TMS/SWDIO
- SWD
- Board Ident: PC13=0
- (near U2) PWR_EXT
- SWCLK
- SWDIO
- Jumpers ON  --> NUCLEO Selected
  Jumpers OFF --> ST-LINK Selected
- (near CN5) TX
- COM
- (near CN5) RX
- T_JRST
- (near CN1) USB ST-LINK
- (near R18) Not Fitted
- (near U3) PWR

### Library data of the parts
C1-C4 C8 C10 C12 C13 = Capacitor_ST: Capacitor 0402 / 0603 / 0805
C5-C7 = Capacitor_ST: Capacitor 0402 / 0603 / 0805; Value: 100nF
C9 C14 = CAP SMD 0603  X5R 1µF 25V 10%: as C20 on sheet MB1137
C15 = CAP SMD 0603  X7R 10000PF 50V 10%: 0603  X7R 10NF; Order code RS: 2040779; Rated voltage: 50V; Tolerance: 10%
CN1 = 1050170001: Silkscreen: USB
CN2 CN3 JP1 JP2 = JP2
CN4 = Header 4: Header, 4-Pin, Single row
CN5 = JP2: Fitted: NO
CN6 = Header 6X1: Header, 6-Pin, Single row
D1 D3-D5 = BAT60JFILM: Manuf_1: STM; Provided: ST; ECCN_US/EU: EAR99/NEC
D2 = Diode: Default Diode; Code - JEDEC: DO-214-AB; Ordered by: STM; ECCN_US/EU: EAR99/NEC
LD4 = LD_BICOLOR_CMS: Bicolor Led; Manuf_Part_1: HSMF-A201-A00J1; Manuf_1: Avago Technologies; Ref St: xxxxxx; cap_dec: ----
R1 R5 R6 R9-R11 R13-R15 R17 R19 R20 R22 R23 R26 = Resistor_ST: as R28 on sheet MB1137
R2 R4 = Resistor_ST: as R27 on sheet MB1137
R3 R24 R25 = Resistor_ST: Resistor 0402 / 0603 / 0805; Description: Resistor 0402 or 0603 or 0805; Value: 10K; Fitted: NO
R7 R8 R12 R16 R18 = Res1: Resistor; Value: 1K
SB101 SB103 SB105 SB108 SB110-SB112 = Circuit Breaker_close: Circuit Breaker
SB102 SB104 SB106 SB107 SB109 = Circuit Breaker
T1 = NPN: NPN Bipolar Transistor; Code - JEDEC: TO-226-AA
U2 = STM32F103CBT6: Medium-density performance line ARM-based 32-bit MCU with 64KB Flash; Manuf_Part_1: STM32F103C8T6; Manuf_1: STM; Ref St: 9175981; Provided: ST; ECCN_US/EU: 3A991A2/NEC
U3 = LD3985M33R: Ultra low drop-low noise BiCMOS voltage, regulators low ESR capacitors compatible; Manuf_1: STM; Provided: ST; Ref St: 9176161; ECCN_US/EU: EAR99/NEC
X1 = XTAL: Crystal Oscillator

## Sheet Ethernet.SchDoc: Ethernet PHY with RJ45 connector
size A4; Author: A.B; CompanyName: STMicroelectronics; Address1: 12, Rue Jules HOROWITZ; Address2: 38019 Grenoble; Address3: FRANCE; DocumentNumber: MB1137; Revision: B-01; SheetNumber: 5; SheetTotal: 6; Project: NUCLEO-XXXXZX
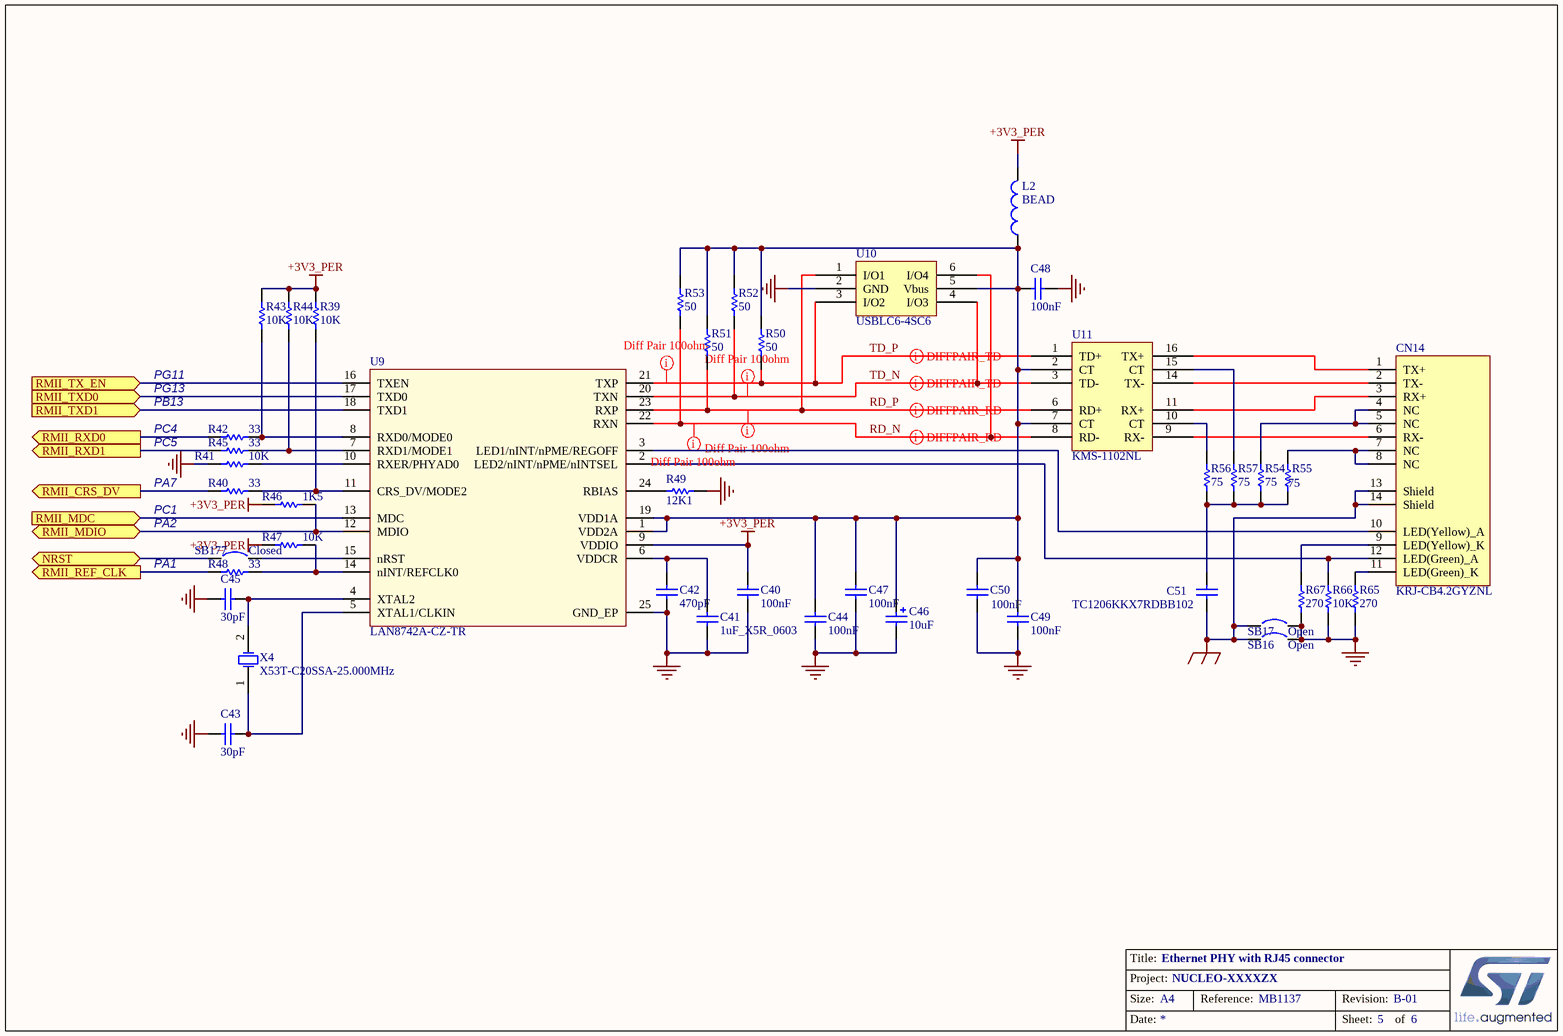
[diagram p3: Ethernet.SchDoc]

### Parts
C40  100nF  [0603C]
C41  1uF_X5R_0603  [0603C]
C42  470pF  [0603C]
C43  30pF  [0603C]
C44  100nF  [0603C]
C45  30pF  [0603C]
C46  10uF  [TAN-A]
C47  100nF  [0603C]
C48  100nF  [0603C]
C49  100nF  [0603C]
C50  100nF  [0603C]
C51  TC1206KKX7RDBB102  [1206C]
CN14  KRJ-CB4.2GYZNL  [RJ45_KRJ-CB4.2GYZNL]
L2  BEAD  [0603L]
R39  10K  [0603R]
R40  33  [0603R]
R41  10K  [0603R]
R42  33  [0603R]
R43  10K  [0603R]
R44  10K  [0603R]
R45  33  [0603R]
R46  1K5  [0603R]
R47  10K  [0603R]
R48  33  [0603R]
R49  12K1  [0603R]
R50  50  [0603R]
R51  50  [0603R]
R52  50  [0603R]
R53  50  [0603R]
R54  75  [0603R]
R55  75  [0603R]
R56  75  [0603R]
R57  75  [0603R]
R65  270  [0603R]
R66  10K  [0603R]
R67  270  [0603R]
SB16  Open  [SB_0603]
SB17  Open  [SB_0603]
SB177  Closed  [SB_0603]
U9  LAN8742A-CZ-TR  [QFN24_0R5_4X4]
U10  USBLC6-4SC6  [SOT23-6L]
U11  KMS-1102NL  [Transformer]
X4  X53T-C20SSA-25.000MHz  [XTAL_2SM_5R0X3R2]

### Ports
NRST, RMII_CRS_DV (out), RMII_MDC (in), RMII_MDIO (bidir), RMII_REF_CLK (out), RMII_RXD0 (out), RMII_RXD1 (out), RMII_TX_EN (in), RMII_TXD0 (in), RMII_TXD1 (in)

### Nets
+3V3_PER: C40.2 L2.2 R39.1 R43.1 R44.1 R46.2 R47.1 U9.9(VDDIO)
EGND: C51.1 CN14.13(Shield) CN14.14(Shield) SB16.1 SB17.1
GND: C40.1 C41.2 C42.1 C43.2 C44.1 C45.2 C46.2 C47.1 C48.1 C49.1 C50.1 R41.2 R49.2 R65.2 R66.2 R67.2 SB16.2 SB17.2 U9.25(GND_EP) U10.2(GND)
NRST: SB177.1 ; port NRST
RD_N: R53.1 U9.22(RXN) U10.6(I/O4) U11.8(RD-)
RD_P: R51.1 U9.23(RXP) U10.1(I/O1) U11.6(RD+)
TD_N: R52.1 U9.20(TXN) U10.4(I/O3) U11.3(TD-)
TD_P: R50.1 U9.21(TXP) U10.3(I/O2) U11.1(TD+)
NetC41_1: C41.1 C42.2 U9.6(VDDCR)
NetC43_1: C43.1 U9.5(XTAL1/CLKIN) X4.1(OSC1)
NetC44_2: C44.2 C46.1 C47.2 C48.2 C49.2 C50.2 L2.1 R50.2 R51.2 R52.2 R53.2 U9.1(VDD2A) U9.19(VDD1A) U10.5(Vbus) U11.2(CT) U11.7(CT)
NetC45_1: C45.1 U9.4(XTAL2) X4.2(OSC2)
NetC51_2: C51.2 R54.1 R55.1 R56.1 R57.1
NetCN9_15: R40.2 ; port RMII_CRS_DV
NetCN14_1: CN14.1(TX+) U11.16(TX+)
NetCN14_2: CN14.2(TX-) U11.14(TX-)
NetCN14_3: CN14.3(RX+) U11.11(RX+)
NetCN14_4: CN14.4(NC) CN14.5(NC) R54.2
NetCN14_6: CN14.6(RX-) U11.9(RX-)
NetCN14_7: CN14.7(NC) CN14.8(NC) R55.2
NetCN14_9: CN14.9(LED(Yellow)_K) R67.1
NetCN14_10: CN14.10(LED(Yellow)_A) U9.3(LED1/nINT/nPME/REGOFF)
NetCN14_11: CN14.11(LED(Green)_K) R65.1
NetCN14_12: CN14.12(LED(Green)_A) R66.1 U9.2(LED2/nINT/nPME/nINTSEL)
NetJP7_1: U9.18(TXD1) ; port RMII_TXD1
NetR39_2: R39.2 R40.1 U9.11(CRS_DV/MODE2)
NetR41_1: R41.1 U9.10(RXER/PHYAD0)
NetR42_1: R42.1 R43.2 U9.8(RXD0/MODE0)
NetR42_2: R42.2 ; port RMII_RXD0
NetR44_2: R44.2 R45.1 U9.7(RXD1/MODE1)
NetR45_2: R45.2 ; port RMII_RXD1
NetR46_1: R46.1 U9.12(MDIO) ; port RMII_MDIO
NetR47_2: R47.2 R48.1 U9.14(nINT/REFCLK0)
NetR48_2: R48.2 ; port RMII_REF_CLK
NetR49_1: R49.1 U9.24(RBIAS)
NetR56_2: R56.2 U11.10(CT)
NetR57_2: R57.2 U11.15(CT)
NetSB164_1: U9.13(MDC) ; port RMII_MDC
NetSB177_2: SB177.2 U9.15(nRST)
NetSB182_2: U9.17(TXD0) ; port RMII_TXD0
NetSB183_2: U9.16(TXEN) ; port RMII_TX_EN

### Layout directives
differential pair: RD_N, RD_P, TD_N, TD_P
rule Matched Net Lengths [Tolerance = 100mil]: RD_N, RD_P, TD_N, TD_P

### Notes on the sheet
- PG11
- PG13
- PB13
- PC4
- PC5
- PA7
- PC1
- PA2
- PA1

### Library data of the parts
C40 C44 C47-C50 = Capacitor_ST: Capacitor 0402 / 0603 / 0805
C41 = CAP SMD 0603  X5R 1µF 25V 10%: as C20 on sheet MB1137
C42 C43 C45 = Capacitor_ST: as C5 on sheet ST_LINK_V2-1
C46 = Cap_10uF_POL_10%_TANA: Polarized Capacitor,10uF,10V,10%,typeA,VISHAY; Manuf_Part_1: 293D106X9010A2TE3
C51 = Capacitor_ST: Capacitor 0402 / 0603 / 0805/ 1206; Value: 100nF
CN14 = KRJ-CB4.2GYZNL: 100 Base-TX (Fast Ethernet) SMD RJ45 single port (1x1) with LEDS Integrated Magnetics Connector; Manuf_1: HanRun; Manuf_Part_1: HR961160C; Manuf_2: Pulse Electronics Corporation; Manuf_Part_2: J3011G21DNLT; Manuf_3: K.O.D International Holding; Manuf_Part_3: RMT-119A-12F6-GY-04
L2 = Inductor: Value: 100uH
R39 R41 R43 R44 R47 R66 = Resistor_ST: as R27 on sheet MB1137
R40 R42 R45 R48 = Res_33_1%_0402: Resistor,33,0402,1%,YAGEO; Manuf_Part_1: RC0402FR-0733RL
R46 = Res_1K5_1%_0402: Resistor,1K5,0402,1%,YAGEO; Manuf_Part_1: RC0402FR-071K5L
R49 = Res_12K1_1%_0603: Resistor,12K1,0603,1%,VISHAY; Manuf_Part_1: MCT 0603-50 1% P5 12K1; Order: 2325243
R50-R53 = Res_50_1%_0603: Resistor,50,0603,1%,YAGEO; Manuf_Part_1: RC0402FR-0750RL; Description: Resistor,50,0402,1%,YAGEO
R54-R57 = Res_75_1%_0603: Resistor,75,0603,1%,YAGEO; Manuf_Part_1: RC0402FR-0750RL; Description: Resistor,50,0402,1%,YAGEO; Value: 50
R65 R67 = Resistor_ST: as R28 on sheet MB1137
SB16 SB17 = Circuit Breaker
SB177 = Circuit Breaker_close: Circuit Breaker
U9 = LAN8742A-CZ-TR: LAN8742A-CZ-TR - Small Footprint RMII 10/100 Ethernet, Transceiver with HP Auto-MDIX and flexPWR Technology SQFN-24; Manuf_1: MICROCHIP
X4 = XTAL_5032: Crystal Oscillator

## Sheet MCU_144.SchDoc: MCU
size A3; DocumentNumber: MB1137; Revision: B-01; SheetNumber: 2; SheetTotal: 6; Project: NUCLEO-XXXXZX
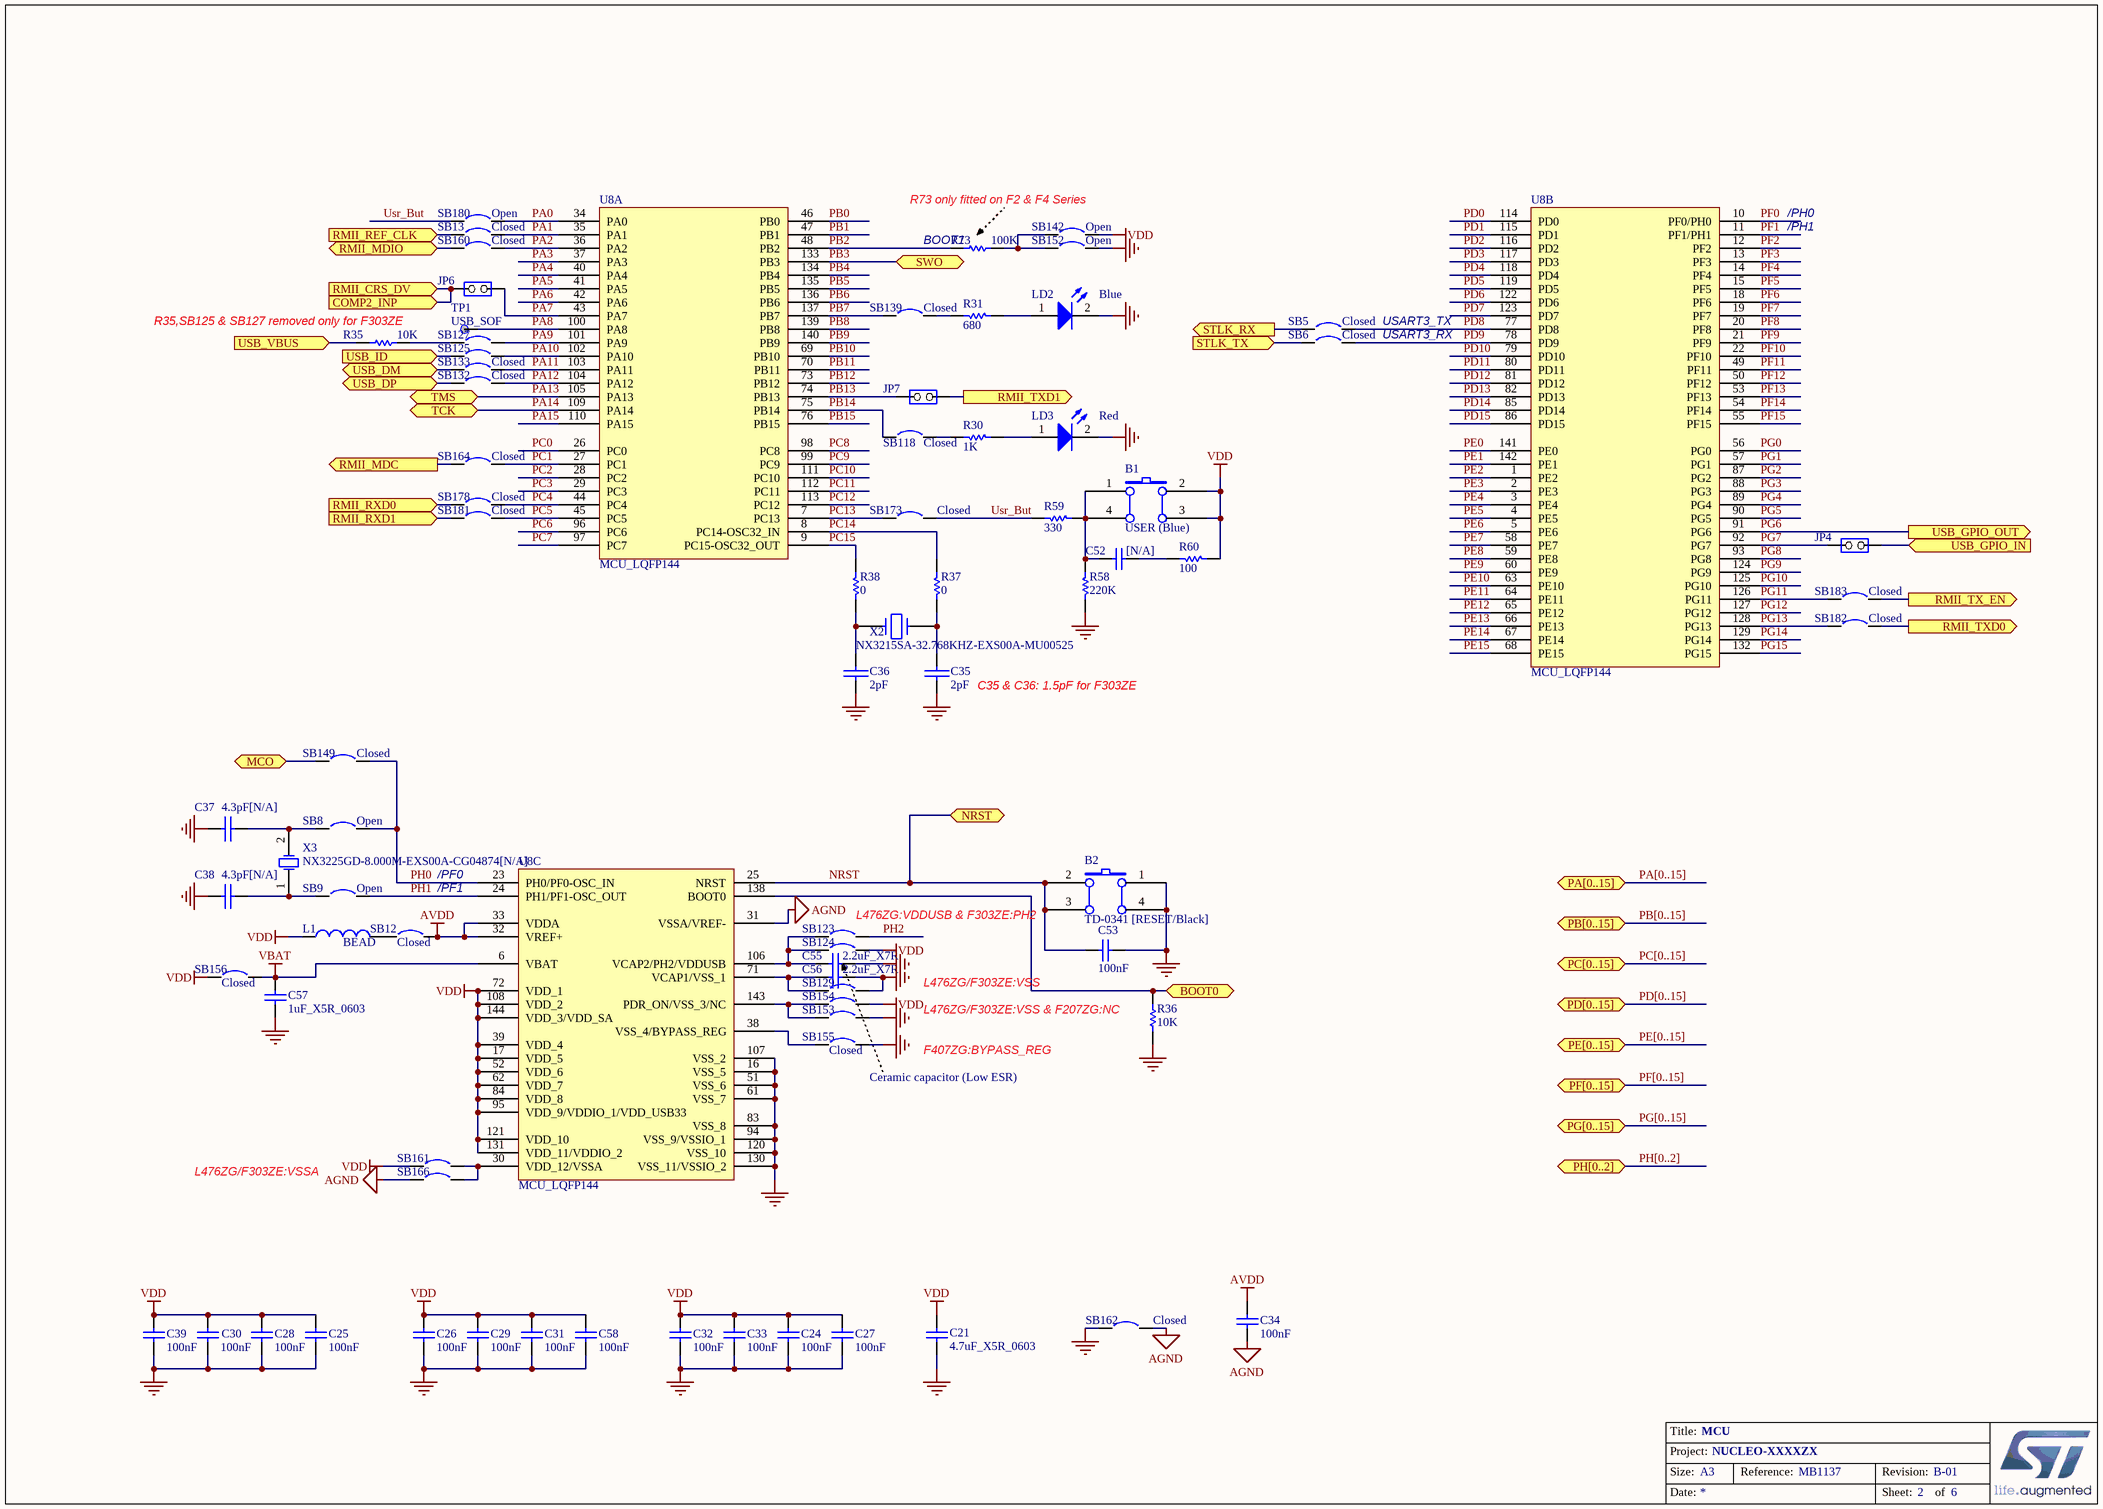
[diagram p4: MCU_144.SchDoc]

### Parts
B1  USER (Blue)  [PB-6X6mm-Blue]
B2  TD-0341 [RESET/Black]  [PB-6X6mm-Black]
C21  4.7uF_X5R_0603  [0603C]
C24  100nF  [0603C]
C25  100nF  [0603C]
C26  100nF  [0603C]
C27  100nF  [0603C]
C28  100nF  [0603C]
C29  100nF  [0603C]
C30  100nF  [0603C]
C31  100nF  [0603C]
C32  100nF  [0603C]
C33  100nF  [0603C]
C34  100nF  [0603C]
C35  2pF  [0603C]
C36  2pF  [0603C]
C37  4.3pF[N/A]  [0603C]
C38  4.3pF[N/A]  [0603C]
C39  100nF  [0603C]
C52  [N/A]  [0603C]
C53  100nF  [0603C]
C55  2.2uF_X7R  [TAN-A]
C56  2.2uF_X7R  [TAN-A]
C57  1uF_X5R_0603  [0603C]
C58  100nF  [0603C]
JP4  (no value)  [HDR_1x2_2R54_V_M_S]
JP6  (no value)  [HDR_1x2_2R54_V_M_S]
JP7  (no value)  [HDR_1x2_2R54_V_M_S]
L1  BEAD  [0603L]
LD2  Blue  [0603D-B]
LD3  Red  [0603D-R]
R30  1K  [0603R]
R31  680  [0603R]
R35  10K  [0603R]
R36  10K  [0603R]
R37  0  [0603R]
R38  0  [0603R]
R58  220K  [0603R]
R59  330  [0603R]
R60  100  [0603R]
R73  100K  [0603R]
SB5  Closed  [SB_0603]
SB6  Closed  [SB_0603]
SB8  Open  [SB_0603]
SB9  Open  [SB_0603]
SB12  Closed  [SB_0603]
SB13  Closed  [SB_0603]
SB118  Closed  [SB_0603]
SB123  Circuit Breaker  [SB_0603]  (value not drawn)
SB124  Circuit Breaker  [SB_0603]  (value not drawn)
SB125  Circuit Breaker  [SB_0603]  (value not drawn)
SB127  Circuit Breaker  [SB_0603]  (value not drawn)
SB129  Circuit Breaker  [SB_0603]  (value not drawn)
SB132  Closed  [SB_0603]
SB133  Closed  [SB_0603]
SB139  Closed  [SB_0603]
SB142  Open  [SB_0603]
SB149  Closed  [SB_0603]
SB152  Open  [SB_0603]
SB153  Circuit Breaker  [SB_0603]  (value not drawn)
SB154  Circuit Breaker  [SB_0603]  (value not drawn)
SB155  Closed  [SB_0603]
SB156  Closed  [SB_0603]
SB160  Closed  [SB_0603]
SB161  Circuit Breaker  [SB_0603]  (value not drawn)
SB162  Closed  [SB_0603]
SB164  Closed  [SB_0603]
SB166  Circuit Breaker  [SB_0603]  (value not drawn)
SB173  Closed  [SB_0603]
SB178  Closed  [SB_0603]
SB180  Open  [SB_0603]
SB181  Closed  [SB_0603]
SB182  Closed  [SB_0603]
SB183  Closed  [SB_0603]
TP1  USB_SOF  [TP]
U8  MCU_LQFP144  [LQFP144_0R5_SKT]  (parts A,B,C of 3)
X2  NX3215SA-32.768KHZ-EXS00A-MU00525  [XTAL_2SM_3R2X1R5]
X3  NX3225GD-8.000M-EXS00A-CG04874[N/A]  [OSC_2SM_3R2x2R5]

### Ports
BOOT0, COMP2_INP (in), MCO, NRST, PA[0..15] (bidir), PB[0..15] (bidir), PC[0..15] (bidir), PD[0..15] (bidir), PE[0..15] (bidir), PF[0..15] (bidir), PG[0..15] (bidir), PH[0..2] (bidir), RMII_CRS_DV (in), RMII_MDC (out), RMII_MDIO (bidir), RMII_REF_CLK (in), RMII_RXD0 (in), RMII_RXD1 (in), RMII_TX_EN (out), RMII_TXD0 (out), RMII_TXD1 (out), STLK_RX (out), STLK_TX (in), SWO, TCK, TMS, USB_DM (bidir), USB_DP (bidir), USB_GPIO_IN (in), USB_GPIO_OUT (out), USB_ID (in), USB_VBUS (in)

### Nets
AGND: C34.2 SB162.2 SB166.1 U8.31(VSSA/VREF-)
AVDD: C34.1 SB12.2 U8.32(VREF+) U8.33(VDDA)
GND: B2.1(A0) B2.4(A1) C21.2 C24.2 C25.2 C26.2 C27.2 C28.2 C29.2 C30.2 C31.2 C32.2 C33.2 C35.2 C36.2 C37.2 C38.2 C39.2 C53.1 C55.2 C56.2 C57.2 C58.2 LD2.2(K) LD3.2(K) R36.2 R58.2 SB129.2 SB152.2 SB153.2 SB155.2 SB162.1 U8.16(VSS_5) U8.51(VSS_6) U8.61(VSS_7) U8.83(VSS_8) U8.94(VSS_9/VSSIO_1) U8.107(VSS_2) U8.120(VSS_10) U8.130(VSS_11/VSSIO_2)
VBAT: C57.1 SB156.2 U8.6(VBAT)
VDD: B1.2(B0) B1.3(B1) C21.1 C24.1 C25.1 C26.1 C27.1 C28.1 C29.1 C30.1 C31.1 C32.1 C33.1 C39.1 C58.1 L1.1 R60.1 SB124.2 SB142.2 SB154.2 SB156.1 SB161.1 U8.17(VDD_5) U8.39(VDD_4) U8.52(VDD_6) U8.62(VDD_7) U8.72(VDD_1) U8.84(VDD_8) U8.95(VDD_9/VDDIO_1/VDD_USB33) U8.108(VDD_2) U8.121(VDD_10) U8.131(VDD_11/VDDIO_2) U8.144(VDD_3/VDD_SA)
BOOT0: R36.1 U8.138(BOOT0) ; port BOOT0
MCO: SB149.1 ; port MCO
NRST: B2.2(B0) B2.3(B1) C53.2 U8.25(NRST) ; port NRST
PA0: SB180.2 U8.34(PA0)
PA1: SB13.2 U8.35(PA1)
PA2: SB160.2 U8.36(PA2)
PA3: U8.37(PA3)
PA4: U8.40(PA4)
PA5: U8.41(PA5)
PA6: U8.42(PA6)
PA7: JP6.1(COMMON) U8.43(PA7)
PA8: TP1.1 U8.100(PA8)
PA9: SB127.2 U8.101(PA9)
PA10: SB125.2 U8.102(PA10)
PA11: SB133.2 U8.103(PA11)
PA12: SB132.2 U8.104(PA12)
PA13: U8.105(PA13) ; port TMS
PA14: U8.109(PA14) ; port TCK
PA15: U8.110(PA15)
PB0: U8.46(PB0)
PB1: U8.47(PB1)
PB2: R73.1 U8.48(PB2)
PB3: U8.133(PB3) ; port SWO
PB4: U8.134(PB4)
PB5: U8.135(PB5)
PB6: U8.136(PB6)
PB7: SB139.1 U8.137(PB7)
PB8: U8.139(PB8)
PB9: U8.140(PB9)
PB10: U8.69(PB10)
PB11: U8.70(PB11)
PB12: U8.73(PB12)
PB13: JP7.2(NO) U8.74(PB13)
PB14: SB118.1 U8.75(PB14)
PB15: U8.76(PB15)
PC0: U8.26(PC0)
PC1: SB164.2 U8.27(PC1)
PC2: U8.28(PC2)
PC3: U8.29(PC3)
PC4: SB178.2 U8.44(PC4)
PC5: SB181.2 U8.45(PC5)
PC6: U8.96(PC6)
PC7: U8.97(PC7)
PC8: U8.98(PC8)
PC9: U8.99(PC9)
PC10: U8.111(PC10)
PC11: U8.112(PC11)
PC12: U8.113(PC12)
PC13: SB173.1 U8.7(PC13)
PC14: R37.2 U8.8(PC14-OSC32_IN)
PC15: R38.2 U8.9(PC15-OSC32_OUT)
PD0: U8.114(PD0)
PD1: U8.115(PD1)
PD2: U8.116(PD2)
PD3: U8.117(PD3)
PD4: U8.118(PD4)
PD5: U8.119(PD5)
PD6: U8.122(PD6)
PD7: U8.123(PD7)
PD8: SB5.2 U8.77(PD8)
PD9: SB6.2 U8.78(PD9)
PD10: U8.79(PD10)
PD11: U8.80(PD11)
PD12: U8.81(PD12)
PD13: U8.82(PD13)
PD14: U8.85(PD14)
PD15: U8.86(PD15)
PE0: U8.141(PE0)
PE1: U8.142(PE1)
PE2: U8.1(PE2)
PE3: U8.2(PE3)
PE4: U8.3(PE4)
PE5: U8.4(PE5)
PE6: U8.5(PE6)
PE7: U8.58(PE7)
PE8: U8.59(PE8)
PE9: U8.60(PE9)
PE10: U8.63(PE10)
PE11: U8.64(PE11)
PE12: U8.65(PE12)
PE13: U8.66(PE13)
PE14: U8.67(PE14)
PE15: U8.68(PE15)
PF0: U8.10(PF0/PH0)
PF1: U8.11(PF1/PH1)
PF2: U8.12(PF2)
PF3: U8.13(PF3)
PF4: U8.14(PF4)
PF5: U8.15(PF5)
PF6: U8.18(PF6)
PF7: U8.19(PF7)
PF8: U8.20(PF8)
PF9: U8.21(PF9)
PF10: U8.22(PF10)
PF11: U8.49(PF11)
PF12: U8.50(PF12)
PF13: U8.53(PF13)
PF14: U8.54(PF14)
PF15: U8.55(PF15)
PG0: U8.56(PG0)
PG1: U8.57(PG1)
PG2: U8.87(PG2)
PG3: U8.88(PG3)
PG4: U8.89(PG4)
PG5: U8.90(PG5)
PG6: U8.91(PG6) ; port USB_GPIO_OUT
PG7: JP4.2(NO) U8.92(PG7)
PG8: U8.93(PG8)
PG9: U8.124(PG9)
PG10: U8.125(PG10)
PG11: SB183.1 U8.126(PG11)
PG12: U8.127(PG12)
PG13: SB182.1 U8.128(PG13)
PG14: U8.129(PG14)
PG15: U8.132(PG15)
PH0: SB8.2 SB149.2 U8.23(PH0/PF0-OSC_IN)
PH1: SB9.2 U8.24(PH1/PF1-OSC_OUT)
PH2: SB123.2
Usr_But: R59.2 SB173.2 SB180.1
NetB1_1: B1.1(A0) B1.4(A1) C52.2 R58.1 R59.1
NetC35_1: C35.1 R37.1 X2.2
NetC36_1: C36.1 R38.1 X2.1
NetC37_1: C37.1 SB8.1 X3.2(OSC2)
NetC38_1: C38.1 SB9.1 X3.1(OSC1)
NetC52_1: C52.1 R60.2
NetC54_1: R35.1 ; port USB_VBUS
NetC55_1: C55.1 SB123.1 SB124.1 U8.106(VCAP2/PH2/VDDUSB)
NetC56_1: C56.1 SB129.1 U8.71(VCAP1/VSS_1)
NetCN5_1: SB5.1 ; port STLK_RX
NetCN5_2: SB6.1 ; port STLK_TX
NetCN9_15: JP6.2(NO) ; port RMII_CRS_DV, port COMP2_INP
NetCN13_2: SB133.1 ; port USB_DM
NetCN13_3: SB132.1 ; port USB_DP
NetCN13_4: SB125.1 ; port USB_ID
NetJP4_1: JP4.1(COMMON) ; port USB_GPIO_IN
NetJP7_1: JP7.1(COMMON) ; port RMII_TXD1
NetL1_2: L1.2 SB12.1
NetLD2_1: LD2.1(A) R31.2
NetLD3_1: LD3.1(A) R30.2
NetR30_1: R30.1 SB118.2
NetR31_1: R31.1 SB139.2
NetR35_2: R35.2 SB127.1
NetR42_2: SB178.1 ; port RMII_RXD0
NetR45_2: SB181.1 ; port RMII_RXD1
NetR46_1: SB160.1 ; port RMII_MDIO
NetR48_2: SB13.1 ; port RMII_REF_CLK
NetR73_2: R73.2 SB142.1 SB152.1
NetSB153_1: SB153.1 SB154.1 U8.143(PDR_ON/VSS_3/NC)
NetSB155_1: SB155.1 U8.38(VSS_4/BYPASS_REG)
NetSB161_2: SB161.2 SB166.2 U8.30(VDD_12/VSSA)
NetSB164_1: SB164.1 ; port RMII_MDC
NetSB182_2: SB182.2 ; port RMII_TXD0
NetSB183_2: SB183.2 ; port RMII_TX_EN

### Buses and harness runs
bus PA[0..15] = port PA[0..15]
bus PB[0..15] = port PB[0..15]
bus PC[0..15] = port PC[0..15]
bus PD[0..15] = port PD[0..15]
bus PE[0..15] = port PE[0..15]
bus PF[0..15] = port PF[0..15]
bus PG[0..15] = port PG[0..15]
bus PH[0..2] = port PH[0..2]

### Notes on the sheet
- R73 only fitted on F2 & F4 Series
- (near R73) BOOT1
- /PH0
- /PH1
- (near R35) R35,SB125 & SB127 removed only for F303ZE
- USART3_TX
- USART3_RX
- (near C35) C35 & C36: 1.5pF for F303ZE
- /PF0
- /PF1
- (near SB123) L476ZG:VDDUSB & F303ZE:PH2
- L476ZG/F303ZE:VSS
- L476ZG/F303ZE:VSS & F207ZG:NC
- F407ZG:BYPASS_REG
- (near SB155) Ceramic capacitor (Low ESR)
- L476ZG/F303ZE:VSSA

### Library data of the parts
B1 B2 = SW PUSHBUTTON: SE PUSHBUTTON
C21 = CAP SMD 0603  X5R 1µF 25V 10%: 0603  X5R 4.7uF; Value: 1µF; Rated voltage: 25V; Tolerance: 10%
C24-C34 C39 C58 = Cap: Capacitor; Value: 10nF
C35-C38 = CAP: Capacitor
C52 C53 = CAP: Capacitor; Value: 100pF
C55 C56 = Cap_2.2uF_X7R_10%_0805: Capacitor,2.2uF,16V, X7R,10%,0805,YAGEO; Manuf_Part_1: CC0805KKX7R7BB225
C57 = CAP SMD 0603  X5R 1µF 25V 10%: as C20 on sheet MB1137
JP4 JP6 JP7 = JP2
L1 = Inductor: Value: 100uH
LD2 LD3 = LED2: as LD5 on sheet MB1137
R30 = Res1: Resistor
R31 R37 R38 R59 R60 = Res1: Resistor; Value: 1K
R35 = Resistor_ST: as R27 on sheet MB1137
R36 R58 R73 = res1: Resistor; Value: 1K
SB5 SB6 SB12 SB13 SB118 SB132 SB133 SB139 SB149 SB155 SB156 SB160 SB162 SB164 SB173 SB178 SB181-SB183 = Circuit Breaker_close: Circuit Breaker
SB8 SB9 SB142 SB152 SB180 = Circuit Breaker
SB123-SB125 SB127 SB129 SB153 SB154 SB161 SB166 = Circuit Breaker: Solder: NO
TP1 = TP
X2 = CRYSTAL_32K: Crystal
X3 = XTAL: Crystal Oscillator

## Sheet USB.SchDoc: USB
size A4; DocumentNumber: MB1137; Revision: B-01; SheetNumber: 4; SheetTotal: 6; Project: NUCLEO-XXXXZX
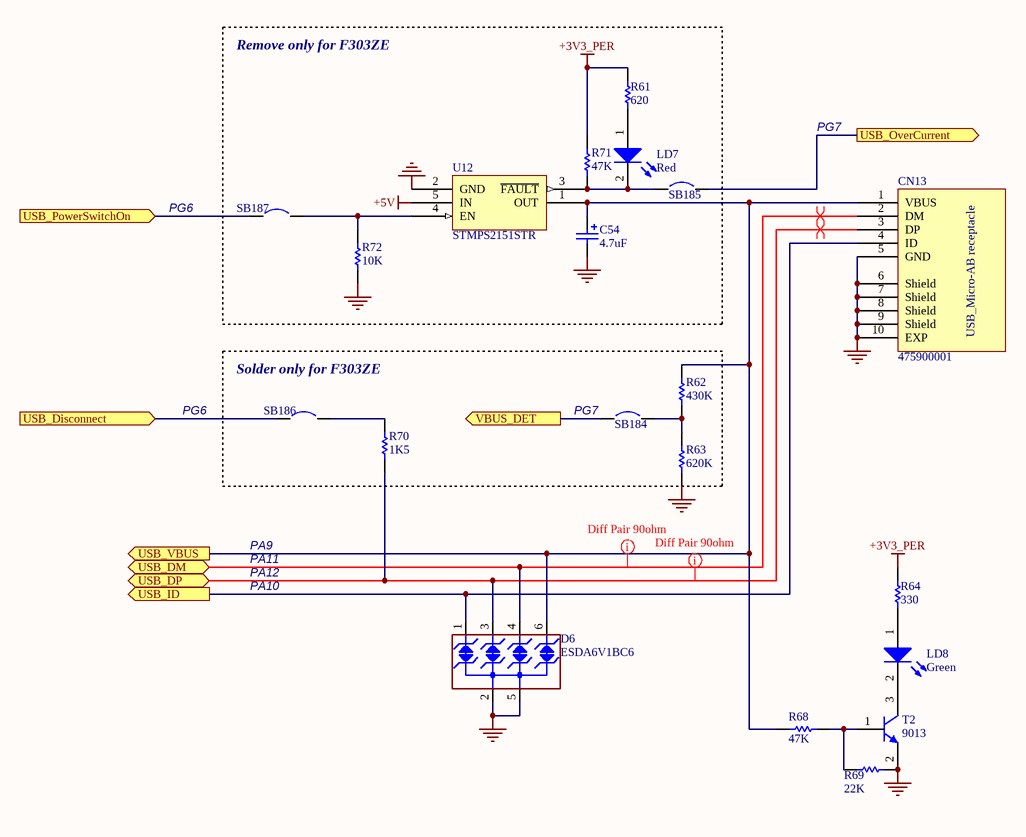
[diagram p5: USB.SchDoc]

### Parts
C54  4.7uF  [TAN-A]
CN13  475900001  [MOLEX_47590001]
D6  ESDA6V1BC6  [SOT23-6L]
LD7  Red  [0603D-R]
LD8  Green  [0603D-G]
R61  620  [0603R]
R62  430K  [0603R]
R63  620K  [0603R]
R64  330  [0603R]
R68  47K  [0603R]
R69  22K  [0603R]
R70  1K5  [0603R]
R71  47K  [0603R]
R72  10K  [0603R]
SB184  Circuit Breaker  [SB_0603]  (value not drawn)
SB185  Circuit Breaker  [SB_0603]  (value not drawn)
SB186  Circuit Breaker  [SB_0603]  (value not drawn)
SB187  Circuit Breaker  [SB_0603]  (value not drawn)
T2  9013  [SOT-23]
U12  STMPS2151STR  [SOT-23-5L]

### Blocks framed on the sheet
Remove only for F303ZE: C54 LD7 R61 R71 R72 SB185 SB187 U12
Solder only for F303ZE: R62 R63 R70 SB184 SB186

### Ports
USB_Disconnect (in), USB_DM (bidir), USB_DP (bidir), USB_ID (out), USB_OverCurrent (out), USB_PowerSwitchOn (in), USB_VBUS (out), VBUS_DET (out)

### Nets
+3V3_PER: R61.2 R64.2 R71.1
+5V: U12.5(IN)
GND: C54.2 CN13.5(GND) CN13.6(Shield) CN13.7(Shield) CN13.8(Shield) CN13.9(Shield) CN13.10(EXP) D6.2(IO2) D6.5(IO4) R63.2 R69.1 R72.1 T2.2(E) U12.2(GND)
PG6: SB186.1 SB187.1 ; port USB_PowerSwitchOn, port USB_Disconnect
NetC54_1: C54.1 CN13.1(VBUS) D6.6(NC) R62.1 R68.1 U12.1(OUT) ; port USB_VBUS
NetCN13_2: CN13.2(DM) D6.4(IO3) ; port USB_DM
NetCN13_3: CN13.3(DP) D6.3(GND) R70.1 ; port USB_DP
NetCN13_4: CN13.4(ID) D6.1(IO1) ; port USB_ID
NetJP4_1: SB184.1 SB185.2 ; port USB_OverCurrent, port VBUS_DET
NetLD7_1: LD7.1(A) R61.1
NetLD7_2: LD7.2(K) R71.2 SB185.1 U12.3(~{FAULT})
NetLD8_1: LD8.1(A) R64.1
NetLD8_2: LD8.2(K) T2.3(C)
NetR62_2: R62.2 R63.1 SB184.2
NetR68_2: R68.2 R69.2 T2.1(B)
NetR70_2: R70.2 SB186.2
NetR72_2: R72.2 SB187.2 U12.4(EN)

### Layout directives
mark named Diff Pair 90ohm: NetCN13_2, NetCN13_3
differential pair: NetCN13_2, NetCN13_3

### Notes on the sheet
- PG7
- PG6
- (near SB184) PG7
- PA9
- PA12
- PA11
- PA10

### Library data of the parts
C54 = Cap Pol1: Polarized Capacitor (Radial); Value: 47uF
D6 = ESDA6V1BC6: 4-line ESD protection; Manuf_1: STM; Manuf_Part_1: ESDA5V3L; Description: Dual Transil array for ESD protection; Ref St: 9179034; Provided: ST; ECCN_US/EU: EAR99/NEC
LD7 LD8 = LED2: as LD5 on sheet MB1137
R61 R72 = Res1: Resistor; Value: 1K
R62-R64 R68 R69 R71 = res1: Resistor; Value: 1K
R70 = Resistor_ST: as R28 on sheet MB1137
SB184-SB187 = Circuit Breaker: Solder: NO
T2 = NPN: as T1 on sheet ST_LINK_V2-1
U12 = STMPS2141STR

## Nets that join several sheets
+3V3: MB1137 (JP5.1 SB2.1 SB3.2), Connectors (CN8.7 CN11.16 SB114.1)
+3V3_PER: MB1137 (SB2.2), Connectors (SB113.1 U7.5), ST_LINK_V2-1 (R25.1), Ethernet (8 pins), USB (R61.2 R64.2 R71.1)
+5V: MB1137 (8 pins), Connectors (CN8.9 CN11.18), ST_LINK_V2-1 (D2.1), USB (U12.5)
AGND: Connectors (CN10.3 CN12.32), MCU_144 (C34.2 SB162.2 SB166.1 U8.31)
AVDD: Connectors (CN7.6 CN10.1 CN12.7), MCU_144 (C34.1 SB12.2 U8.32 U8.33)
E5V: MB1137 (JP3.2), Connectors (CN11.6), ST_LINK_V2-1 (D3.1)
GND: MB1137 (14 pins), Connectors (27 pins), ST_LINK_V2-1 (44 pins), Ethernet (20 pins), MCU_144 (40 pins), USB (14 pins)
U5V: MB1137 (6 pins), Connectors (CN12.8), ST_LINK_V2-1 (5 pins)
VBAT: Connectors (CN11.33), MCU_144 (C57.1 SB156.2 U8.6)
VDD: MB1137 (JP5.2), Connectors (CN11.5), MCU_144 (33 pins)
VIN: MB1137 (C17.1 U5.3), Connectors (CN8.15 CN11.24)
VIN_5V: MB1137 (C18.1 JP3.6 U5.2 U5.4), ST_LINK_V2-1 (D4.1)
BOOT0: Connectors (CN11.7), MCU_144 (R36.1 U8.138)
MCO: ST_LINK_V2-1 (SB112.2), MCU_144 (SB149.1)
NetC54_1: MCU_144 (R35.1), USB (6 pins)
NetCN5_1: ST_LINK_V2-1 (CN5.1 U2.13), MCU_144 (SB5.1)
NetCN5_2: ST_LINK_V2-1 (CN5.2 U2.12), MCU_144 (SB6.1)
NetCN9_15: Connectors (CN9.15 SB136.1), Ethernet (R40.2), MCU_144 (JP6.2)
NetCN13_2: MCU_144 (SB133.1), USB (CN13.2 D6.4)
NetCN13_3: MCU_144 (SB132.1), USB (CN13.3 D6.3 R70.1)
NetCN13_4: MCU_144 (SB125.1), USB (CN13.4 D6.1)
NetJP4_1: MCU_144 (JP4.1), USB (SB184.1 SB185.2)
NetJP7_1: Ethernet (U9.18), MCU_144 (JP7.1)
NetR27_2: MB1137 (R27.2 U4.3), ST_LINK_V2-1 (U2.28)
NetR42_2: Ethernet (R42.2), MCU_144 (SB178.1)
NetR45_2: Ethernet (R45.2), MCU_144 (SB181.1)
NetR46_1: Ethernet (R46.1 U9.12), MCU_144 (SB160.1)
NetR48_2: Ethernet (R48.2), MCU_144 (SB13.1)
NetSB164_1: Ethernet (U9.13), MCU_144 (SB164.1)
NetSB182_2: Ethernet (U9.17), MCU_144 (SB182.2)
NetSB183_2: Ethernet (U9.16), MCU_144 (SB183.2)
NRST: Connectors (CN8.5 CN11.14), ST_LINK_V2-1 (SB111.2), Ethernet (SB177.1), MCU_144 (B2.2 B2.3 C53.2 U8.25)
PA0: Connectors (CN11.28 SB179.1), MCU_144 (SB180.2 U8.34)
PA1: Connectors (CN11.30 SB11.2), MCU_144 (SB13.2 U8.35)
PA2: Connectors (CN12.35 SB159.1), MCU_144 (SB160.2 U8.36)
PA3: Connectors (CN9.1 CN12.37), MCU_144 (U8.37)
PA4: Connectors (CN7.17 CN11.32), MCU_144 (U8.40)
PA5: Connectors (CN7.10 CN12.11 SB119.2), MCU_144 (U8.41)
PA6: Connectors (CN7.12 CN12.13), MCU_144 (U8.42)
PA7: Connectors (CN12.15 SB121.2), MCU_144 (JP6.1 U8.43)
PA8: Connectors (CN12.23 SB115.2), MCU_144 (TP1.1 U8.100)
PA9: Connectors (CN12.21 SB128.2), MCU_144 (SB127.2 U8.101)
PA10: Connectors (CN12.33 SB126.2), MCU_144 (SB125.2 U8.102)
PA11: Connectors (CN12.14), MCU_144 (SB133.2 U8.103)
PA12: Connectors (CN12.12), MCU_144 (SB132.2 U8.104)
PA13: Connectors (CN11.13), ST_LINK_V2-1 (SB108.1), MCU_144 (U8.105)
PA14: Connectors (CN11.15), ST_LINK_V2-1 (SB103.1), MCU_144 (U8.109)
PA15: Connectors (CN7.9 CN11.17), MCU_144 (U8.110)
PB0: Connectors (CN10.31 CN11.34 SB120.1), MCU_144 (U8.46)
PB1: Connectors (CN10.7 CN12.24), MCU_144 (U8.47)
PB2: Connectors (CN10.15 CN12.22 SB137.2), MCU_144 (R73.1 U8.48)
PB3: Connectors (CN7.15 CN12.31), ST_LINK_V2-1 (SB110.2), MCU_144 (U8.133)
PB4: Connectors (CN7.19 CN12.27), MCU_144 (U8.134)
PB5: Connectors (CN7.13 CN12.29 SB122.2), MCU_144 (U8.135)
PB6: Connectors (CN10.13 CN12.17 SB136.2), MCU_144 (U8.136)
PB7: Connectors (CN11.21), MCU_144 (SB139.1 U8.137)
PB8: Connectors (CN7.2 CN12.3 SB138.2), MCU_144 (U8.139)
PB9: Connectors (CN7.4 CN12.5 SB143.2), MCU_144 (U8.140)
PB10: Connectors (CN10.32 CN12.25), MCU_144 (U8.69)
PB11: Connectors (CN10.34 CN12.18), MCU_144 (U8.70)
PB12: Connectors (CN7.7 CN12.16), MCU_144 (U8.73)
PB13: Connectors (CN7.5 CN12.30), MCU_144 (JP7.2 U8.74)
PB14: Connectors (CN12.28), MCU_144 (SB118.1 U8.75)
PB15: Connectors (CN7.3 CN12.26), MCU_144 (U8.76)
PC0: Connectors (CN9.3 CN11.38), MCU_144 (U8.26)
PC1: Connectors (CN11.36 SB165.2), MCU_144 (SB164.2 U8.27)
PC2: Connectors (CN10.9 CN11.35), MCU_144 (U8.28)
PC3: Connectors (CN9.5 CN11.37), MCU_144 (U8.29)
PC4: Connectors (CN12.34 SB150.2 SB151.1), MCU_144 (SB178.2 U8.44)
PC5: Connectors (CN12.6 SB140.2 SB141.1), MCU_144 (SB181.2 U8.45)
PC6: Connectors (CN7.1 CN12.4), MCU_144 (U8.96)
PC7: Connectors (CN7.11 CN12.19), MCU_144 (U8.97)
PC8: Connectors (CN8.2 SB116.1), MCU_144 (U8.98)
PC9: Connectors (CN8.4 SB117.1), MCU_144 (U8.99)
PC10: Connectors (CN8.6 CN11.1), MCU_144 (U8.111)
PC11: Connectors (CN8.8 CN11.2), MCU_144 (U8.112)
PC12: Connectors (CN8.10 CN11.3), MCU_144 (U8.113)
PC13: Connectors (CN11.23), MCU_144 (SB173.1 U8.7)
PC14: Connectors (SB144.1), MCU_144 (R37.2 U8.8)
PC15: Connectors (SB145.1), MCU_144 (R38.2 U8.9)
PD0: Connectors (CN9.25 CN11.57), MCU_144 (U8.114)
PD1: Connectors (CN9.27 CN11.55), MCU_144 (U8.115)
PD2: Connectors (CN8.12 CN11.4), MCU_144 (U8.116)
PD3: Connectors (CN9.10 CN11.40), MCU_144 (U8.117)
PD4: Connectors (CN9.8 CN11.39), MCU_144 (U8.118)
PD5: Connectors (CN9.6 CN11.41), MCU_144 (U8.119)
PD6: Connectors (CN9.4 CN11.43), MCU_144 (U8.122)
PD7: Connectors (CN9.2 CN11.45), MCU_144 (U8.123)
PD8: Connectors (SB7.2), MCU_144 (SB5.2 U8.77)
PD9: Connectors (SB4.1), MCU_144 (SB6.2 U8.78)
PD10: Connectors (CN12.65), MCU_144 (U8.79)
PD11: Connectors (CN12.45 SB174.2 SB175.1), MCU_144 (U8.80)
PD12: Connectors (CN12.43 SB171.2 SB172.1), MCU_144 (U8.81)
PD13: Connectors (CN12.41 SB167.2 SB168.1), MCU_144 (U8.82)
PD14: Connectors (CN7.16 CN12.46), MCU_144 (U8.85)
PD15: Connectors (CN7.18 CN12.48), MCU_144 (U8.86)
PE0: Connectors (CN10.33 CN12.64), MCU_144 (U8.141)
PE1: Connectors (CN11.61), MCU_144 (U8.142)
PE2: Connectors (CN9.14 CN10.25 CN11.46), MCU_144 (U8.1)
PE3: Connectors (CN9.22 CN11.47), MCU_144 (U8.2)
PE4: Connectors (CN9.16 CN11.48), MCU_144 (U8.3)
PE5: Connectors (CN9.18 CN11.50), MCU_144 (U8.4)
PE6: Connectors (CN9.20 CN11.62), MCU_144 (U8.5)
PE7: Connectors (CN10.20 CN12.44), MCU_144 (U8.58)
PE8: Connectors (CN10.18 CN12.40), MCU_144 (U8.59)
PE9: Connectors (CN10.4 CN12.52), MCU_144 (U8.60)
PE10: Connectors (CN10.24 CN12.47), MCU_144 (U8.63)
PE11: Connectors (CN10.6 CN12.56), MCU_144 (U8.64)
PE12: Connectors (CN10.26 CN12.49), MCU_144 (U8.65)
PE13: Connectors (CN10.10 CN12.55), MCU_144 (U8.66)
PE14: Connectors (CN10.28 CN12.51), MCU_144 (U8.67)
PE15: Connectors (CN10.30 CN12.53), MCU_144 (U8.68)
PF0: Connectors (CN11.53 SB176.2), MCU_144 (U8.10)
PF1: Connectors (CN11.51 SB170.2), MCU_144 (U8.11)
PF2: Connectors (CN11.52 SB169.2), MCU_144 (U8.12)
PF3: Connectors (CN12.58 SB15.1 SB146.2), MCU_144 (U8.13)
PF4: Connectors (CN12.38 SB158.1), MCU_144 (U8.14)
PF5: Connectors (CN12.36 SB14.1 SB147.2), MCU_144 (U8.15)
PF6: Connectors (CN11.9), MCU_144 (U8.18)
PF7: Connectors (CN9.26 CN11.11), MCU_144 (U8.19)
PF8: Connectors (CN9.24 CN11.54), MCU_144 (U8.20)
PF9: Connectors (CN9.28 CN11.56), MCU_144 (U8.21)
PF10: Connectors (CN12.42 SB10.1 SB157.2), MCU_144 (U8.22)
PF11: Connectors (CN12.62), MCU_144 (U8.49)
PF12: Connectors (CN7.20 CN12.59), MCU_144 (U8.50)
PF13: Connectors (CN10.2 CN12.57), MCU_144 (U8.53)
PF14: Connectors (CN10.8 CN12.50), MCU_144 (U8.54)
PF15: Connectors (CN10.12 CN12.60), MCU_144 (U8.55)
PG0: Connectors (CN9.29 CN11.59), MCU_144 (U8.56)
PG1: Connectors (CN9.30 CN11.58), MCU_144 (U8.57)
PG2: Connectors (CN8.14 CN11.42), MCU_144 (U8.87)
PG3: Connectors (CN8.16 CN11.44), MCU_144 (U8.88)
PG4: Connectors (CN12.69), MCU_144 (U8.89)
PG5: Connectors (CN12.68), MCU_144 (U8.90)
PG6: Connectors (CN12.70), MCU_144 (U8.91), USB (SB186.1 SB187.1)
PG7: Connectors (CN12.67), MCU_144 (JP4.2 U8.92)
PG8: Connectors (CN12.66), MCU_144 (U8.93)
PG9: Connectors (CN11.63 SB130.1 SB134.1), MCU_144 (U8.124)
PG10: Connectors (CN11.66 SB135.1), MCU_144 (U8.125)
PG11: Connectors (CN11.70), MCU_144 (SB183.1 U8.126)
PG12: Connectors (CN11.65), MCU_144 (U8.127)
PG13: Connectors (CN11.68), MCU_144 (SB182.1 U8.128)
PG14: Connectors (CN12.61 SB131.1), MCU_144 (U8.129)
PG15: Connectors (CN11.64), MCU_144 (U8.132)
PH0: Connectors (SB148.1), MCU_144 (SB8.2 SB149.2 U8.23)
PH1: Connectors (SB163.1), MCU_144 (SB9.2 U8.24)
PH2: Connectors (CN11.67), MCU_144 (SB123.2)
